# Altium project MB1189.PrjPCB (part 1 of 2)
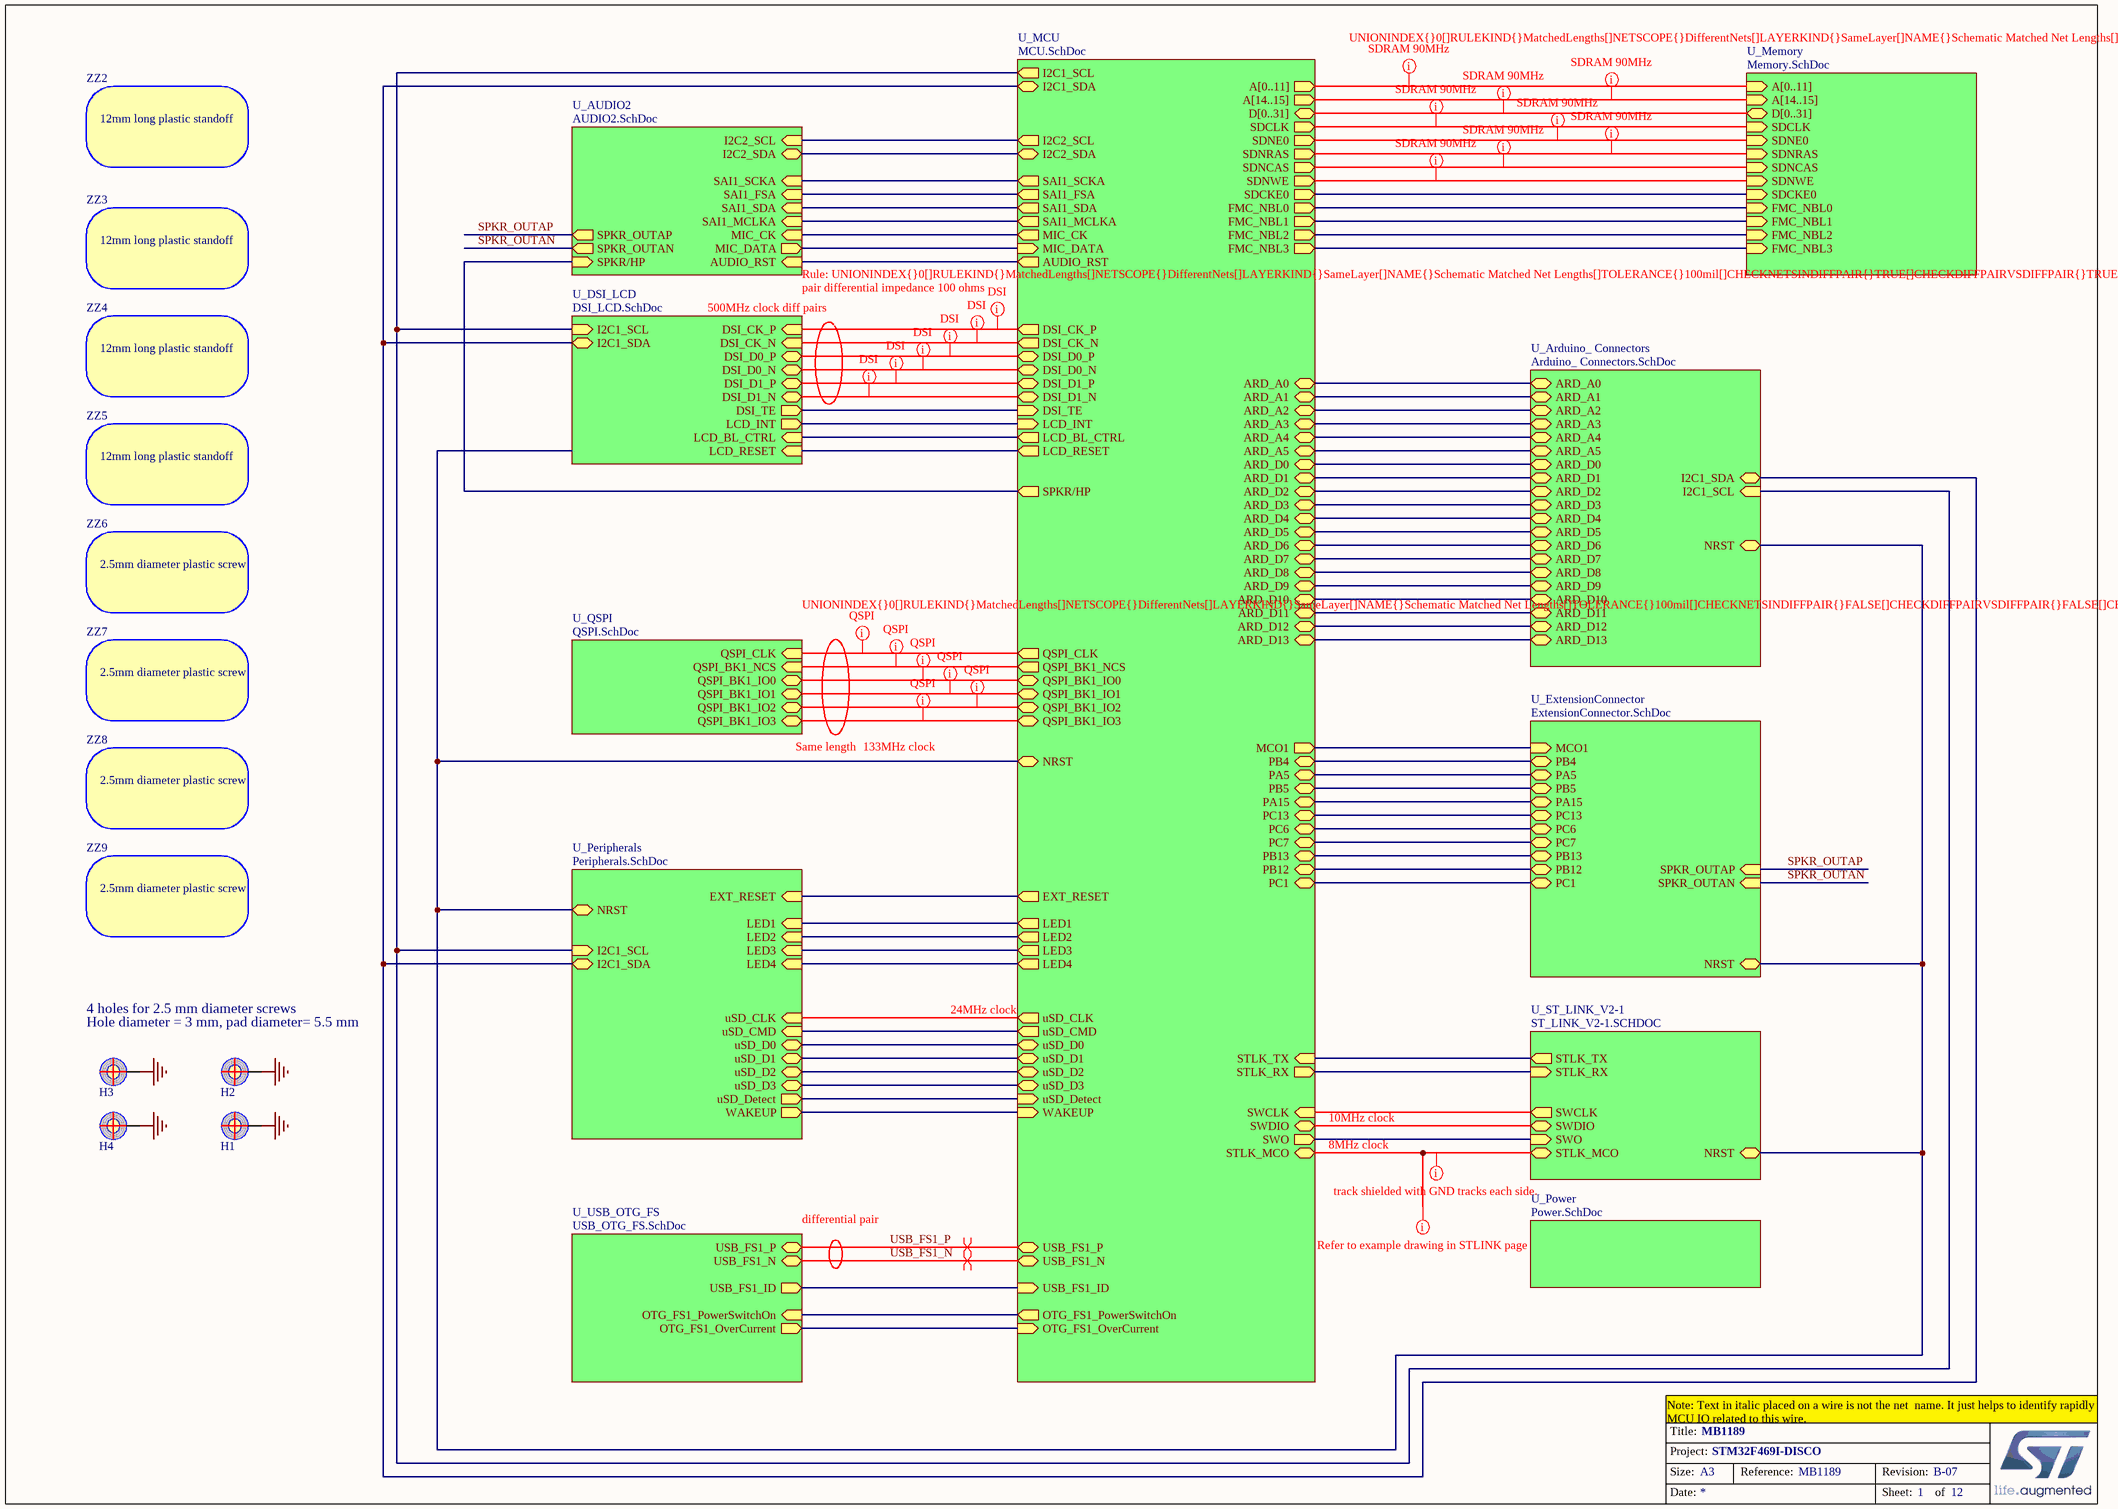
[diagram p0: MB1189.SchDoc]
12 sheets, 280 parts. Net scope: hierarchical (ports join the sheet entries above them; power ports are global).
Sheets:
  MB1189.SchDoc
    U_Memory = Memory.SchDoc
    U_Peripherals = Peripherals.SchDoc
    U_Power = Power.SchDoc
    U_ST_LINK_V2-1 = ST_LINK_V2-1.SCHDOC
    U_MCU = MCU.SchDoc
    U_Arduino_ Connectors = Arduino_ Connectors.SchDoc
    U_DSI_LCD = DSI_LCD.SchDoc
    U_QSPI = QSPI.SchDoc
    U_AUDIO2 = AUDIO2.SchDoc
    U_USB_OTG_FS = USB_OTG_FS.SchDoc
    U_ExtensionConnector = ExtensionConnector.SchDoc

## Sheet MB1189.SchDoc: MB1189
size A3; Date: 9/24/2014; Author: P.A.; CompanyName: STMicroelectronics; Organization: Microcontrollers Division; Address1: 12, Rue Jules HOROWITZ; Address2: 38019 Grenoble; Address3: FRANCE; DocumentNumber: MB1189; Revision: B-07; SheetNumber: 1; SheetTotal: 12; Project: STM32F469I-DISCO

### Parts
H1  POSITION HOLE  [HOLE_C5R5D3]  (value not drawn)
H2  POSITION HOLE  [HOLE_C5R5D3]  (value not drawn)
H3  POSITION HOLE  [HOLE_C5R5D3]  (value not drawn)
H4  POSITION HOLE  [HOLE_C5R5D3]  (value not drawn)
ZZ2  12mm long plastic standoff
ZZ3  12mm long plastic standoff
ZZ4  12mm long plastic standoff
ZZ5  12mm long plastic standoff
ZZ6  2.5mm diameter plastic screw
ZZ7  2.5mm diameter plastic screw
ZZ8  2.5mm diameter plastic screw
ZZ9  2.5mm diameter plastic screw

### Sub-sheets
U_Arduino_ Connectors = Arduino_ Connectors.SchDoc: I2C1_SDA (bidir), ARD_A0 (bidir), ARD_A1 (bidir), ARD_A2 (bidir), ARD_A3 (bidir), ARD_A4 (bidir), ARD_A5 (bidir), ARD_D5 (bidir), ARD_D4 (bidir), ARD_D3 (bidir), ARD_D2 (bidir), ARD_D1 (bidir), ARD_D0 (bidir), ARD_D13 (bidir), ARD_D12 (bidir), ARD_D11 (bidir), ARD_D10 (bidir), ARD_D9 (bidir), ARD_D8 (bidir), ARD_D6 (bidir), ARD_D7 (bidir), I2C1_SCL (in), NRST (bidir)
U_AUDIO2 = AUDIO2.SchDoc: SAI1_SCKA (in), SAI1_FSA (in), SAI1_SDA (in), AUDIO_RST (in), SAI1_MCLKA (in), I2C2_SCL (in), I2C2_SDA (bidir), MIC_CK (in), MIC_DATA (out), SPKR_OUTAP (out), SPKR_OUTAN (out), SPKR/HP (in)
U_DSI_LCD = DSI_LCD.SchDoc: DSI_CK_P (in), DSI_CK_N (in), DSI_D0_P (bidir), DSI_D0_N (bidir), DSI_D1_P (bidir), DSI_D1_N (bidir), DSI_TE (out), I2C1_SDA (bidir), I2C1_SCL (in), LCD_BL_CTRL (in), LCD_INT (out), LCD_RESET (in)
U_ExtensionConnector = ExtensionConnector.SchDoc: SPKR_OUTAP (in), SPKR_OUTAN (in), NRST (bidir), MCO1 (in), PB4 (bidir), PA5 (bidir), PB5 (bidir), PA15 (bidir), PC13 (bidir), PC7 (bidir), PC6 (bidir), PB13 (bidir), PB12 (bidir), PC1 (bidir)
U_MCU = MCU.SchDoc: LCD_BL_CTRL (out), MIC_CK (out), I2C1_SCL (out), I2C1_SDA (bidir), uSD_D0 (bidir), uSD_D1 (bidir), uSD_D2 (bidir), EXT_RESET (out), uSD_D3 (bidir), uSD_CLK (out), uSD_CMD (out), FMC_NBL3 (out), FMC_NBL2 (out), FMC_NBL0 (out), FMC_NBL1 (out), SAI1_SDA (out), SAI1_SCKA (out), SAI1_FSA (out), SAI1_MCLKA (out), SDNRAS (out), SDCLK (out), SDNCAS (out), SDCKE0 (out), SDNE0 (out), SDNWE (out), D[0..31] (bidir), QSPI_CLK (out), QSPI_BK1_NCS (out), QSPI_BK1_IO3 (bidir), QSPI_BK1_IO2 (bidir), QSPI_BK1_IO1 (bidir), QSPI_BK1_IO0 (bidir), WAKEUP (in), DSI_TE (in), DSI_CK_P (out), DSI_CK_N (out), DSI_D0_P (bidir), DSI_D0_N (bidir), DSI_D1_P (bidir), DSI_D1_N (bidir), NRST (bidir), LCD_INT (in), LED1 (out), LED2 (out), LED3 (out), LED4 (out), uSD_Detect (in), STLK_TX (in), STLK_RX (out), ARD_D5 (bidir), ARD_D4 (bidir), ARD_D3 (bidir), ARD_D2 (bidir), ARD_D1 (bidir), ARD_D0 (bidir), ARD_D13 (bidir), ARD_D12 (bidir), ARD_D11 (bidir), ARD_D10 (bidir), ARD_D9 (bidir), ARD_D8 (bidir), ARD_D6 (bidir), ARD_D7 (bidir), ARD_A0 (bidir), ARD_A1 (bidir), ARD_A2 (bidir), ARD_A3 (bidir), ARD_A4 (bidir), ARD_A5 (bidir), SWCLK (in), SWO (out), AUDIO_RST (out), USB_FS1_ID (in), OTG_FS1_PowerSwitchOn (out), OTG_FS1_OverCurrent (in), I2C2_SCL (out), I2C2_SDA (bidir), MIC_DATA (in), MCO1 (out), USB_FS1_N (bidir), USB_FS1_P (bidir), SWDIO, SPKR/HP (out), A[0..11] (out), A[14..15] (out), PB4 (bidir), PB5 (bidir), PA5 (bidir), PA15 (bidir), PC7 (bidir), PC6 (bidir), PC13 (bidir), PB12 (bidir), PB13 (bidir), PC1 (bidir), LCD_RESET (out), STLK_MCO
U_Memory = Memory.SchDoc: FMC_NBL0 (in), FMC_NBL1 (in), D[0..31] (bidir), SDNCAS (in), SDNWE (in), SDNRAS (in), SDNE0 (in), SDCKE0 (in), SDCLK (in), FMC_NBL3 (in), FMC_NBL2 (in), A[0..11] (in), A[14..15] (in)
U_Peripherals = Peripherals.SchDoc: uSD_CLK (in), uSD_CMD (in), uSD_D0 (bidir), uSD_D1 (bidir), uSD_D2 (bidir), uSD_D3 (bidir), WAKEUP (out), EXT_RESET (in), LED1 (in), LED2 (in), LED3 (in), LED4 (in), NRST (bidir), uSD_Detect (out), I2C1_SDA (bidir), I2C1_SCL (in)
U_Power = Power.SchDoc: no entries
U_QSPI = QSPI.SchDoc: QSPI_BK1_IO0 (bidir), QSPI_BK1_IO2 (bidir), QSPI_BK1_IO1 (bidir), QSPI_CLK (in), QSPI_BK1_NCS (in), QSPI_BK1_IO3 (bidir)
U_ST_LINK_V2-1 = ST_LINK_V2-1.SCHDOC: STLK_RX (in), STLK_TX (out), SWDIO, SWO (in), SWCLK (out), NRST (bidir), STLK_MCO
U_USB_OTG_FS = USB_OTG_FS.SchDoc: OTG_FS1_PowerSwitchOn (in), OTG_FS1_OverCurrent (out), USB_FS1_ID (out), USB_FS1_N (bidir), USB_FS1_P (bidir)

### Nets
GND: H1.1 H2.1 H3.1 H4.1
AUDIO_RST: sheet U_MCU/AUDIO_RST, sheet U_AUDIO2/AUDIO_RST
HSSI_CLK_N: sheet U_MCU/DSI_CK_N, sheet U_DSI_LCD/DSI_CK_N
HSSI_CLK_P: sheet U_MCU/DSI_CK_P, sheet U_DSI_LCD/DSI_CK_P
HSSI_D0_N: sheet U_MCU/DSI_D0_N, sheet U_DSI_LCD/DSI_D0_N
HSSI_D0_P: sheet U_MCU/DSI_D0_P, sheet U_DSI_LCD/DSI_D0_P
HSSI_D1_N: sheet U_MCU/DSI_D1_N, sheet U_DSI_LCD/DSI_D1_N
HSSI_D1_P: sheet U_MCU/DSI_D1_P, sheet U_DSI_LCD/DSI_D1_P
I2C1_SCL: sheet U_Peripherals/I2C1_SCL, sheet U_MCU/I2C1_SCL, sheet U_Arduino_ Connectors/I2C1_SCL, sheet U_DSI_LCD/I2C1_SCL
I2C1_SDA: sheet U_Peripherals/I2C1_SDA, sheet U_MCU/I2C1_SDA, sheet U_Arduino_ Connectors/I2C1_SDA, sheet U_DSI_LCD/I2C1_SDA
I2C2_SCL: sheet U_MCU/I2C2_SCL, sheet U_AUDIO2/I2C2_SCL
I2C2_SDA: sheet U_MCU/I2C2_SDA, sheet U_AUDIO2/I2C2_SDA
LCD_BL_CTRL: sheet U_MCU/LCD_BL_CTRL, sheet U_DSI_LCD/LCD_BL_CTRL
LCD_INT: sheet U_MCU/LCD_INT, sheet U_DSI_LCD/LCD_INT
LCD_RST: sheet U_MCU/LCD_RESET, sheet U_DSI_LCD/LCD_RESET
NRST: sheet U_Peripherals/NRST, sheet U_ST_LINK_V2-1/NRST, sheet U_MCU/NRST, sheet U_Arduino_ Connectors/NRST, sheet U_ExtensionConnector/NRST
PA0: sheet U_Peripherals/WAKEUP, sheet U_MCU/WAKEUP
PA1: sheet U_MCU/ARD_D3, sheet U_Arduino_ Connectors/ARD_D3
PA2: sheet U_MCU/ARD_D5, sheet U_Arduino_ Connectors/ARD_D5
PA4: sheet U_MCU/ARD_A5, sheet U_Arduino_ Connectors/ARD_A5
PA5: sheet U_MCU/PA5, sheet U_ExtensionConnector/PA5
PA6: sheet U_MCU/ARD_D6, sheet U_Arduino_ Connectors/ARD_D6
PA7: sheet U_MCU/ARD_D9, sheet U_Arduino_ Connectors/ARD_D9
PA8: sheet U_MCU/MCO1, sheet U_ExtensionConnector/MCO1
PA10: sheet U_MCU/USB_FS1_ID, sheet U_USB_OTG_FS/USB_FS1_ID
PA13: sheet U_ST_LINK_V2-1/SWDIO, sheet U_MCU/SWDIO
PA14: sheet U_ST_LINK_V2-1/SWCLK, sheet U_MCU/SWCLK
PA15: sheet U_MCU/PA15, sheet U_ExtensionConnector/PA15
PB0: sheet U_Peripherals/EXT_RESET, sheet U_MCU/EXT_RESET
PB1: sheet U_MCU/ARD_A0, sheet U_Arduino_ Connectors/ARD_A0
PB2: sheet U_MCU/OTG_FS1_PowerSwitchOn, sheet U_USB_OTG_FS/OTG_FS1_PowerSwitchOn
PB4: sheet U_MCU/PB4, sheet U_ExtensionConnector/PB4
PB5: sheet U_MCU/PB5, sheet U_ExtensionConnector/PB5
PB6: sheet U_MCU/QSPI_BK1_NCS, sheet U_QSPI/QSPI_BK1_NCS
PB7: sheet U_MCU/OTG_FS1_OverCurrent, sheet U_USB_OTG_FS/OTG_FS1_OverCurrent
PB10: sheet U_ST_LINK_V2-1/STLK_RX, sheet U_MCU/STLK_RX
PB11: sheet U_ST_LINK_V2-1/STLK_TX, sheet U_MCU/STLK_TX
PB12: sheet U_MCU/PB12, sheet U_ExtensionConnector/PB12
PB13: sheet U_MCU/PB13, sheet U_ExtensionConnector/PB13
PB14: sheet U_MCU/ARD_D12, sheet U_Arduino_ Connectors/ARD_D12
PB15: sheet U_MCU/ARD_D11, sheet U_Arduino_ Connectors/ARD_D11
PC0: sheet U_Memory/SDNWE, sheet U_MCU/SDNWE
PC1: sheet U_MCU/PC1, sheet U_ExtensionConnector/PC1
PC2: sheet U_MCU/ARD_A1, sheet U_Arduino_ Connectors/ARD_A1
PC3: sheet U_MCU/ARD_A2, sheet U_Arduino_ Connectors/ARD_A2
PC4: sheet U_MCU/ARD_A3, sheet U_Arduino_ Connectors/ARD_A3
PC5: sheet U_MCU/ARD_A4, sheet U_Arduino_ Connectors/ARD_A4
PC6: sheet U_MCU/PC6, sheet U_ExtensionConnector/PC6
PC7: sheet U_MCU/PC7, sheet U_ExtensionConnector/PC7
PC8: sheet U_Peripherals/uSD_D0, sheet U_MCU/uSD_D0
PC10: sheet U_Peripherals/uSD_D2, sheet U_MCU/uSD_D2
PC11: sheet U_Peripherals/uSD_D3, sheet U_MCU/uSD_D3
PC12: sheet U_Peripherals/uSD_CLK, sheet U_MCU/uSD_CLK
PC13: sheet U_MCU/PC13, sheet U_ExtensionConnector/PC13
PD2: sheet U_Peripherals/uSD_CMD, sheet U_MCU/uSD_CMD
PD3: sheet U_MCU/ARD_D13, sheet U_Arduino_ Connectors/ARD_D13
PD4: sheet U_Peripherals/LED2, sheet U_MCU/LED2
PD5: sheet U_Peripherals/LED3, sheet U_MCU/LED3
PD6: sheet U_MCU/MIC_DATA, sheet U_AUDIO2/MIC_DATA
PE0: sheet U_Memory/FMC_NBL0, sheet U_MCU/FMC_NBL0
PE1: sheet U_Memory/FMC_NBL1, sheet U_MCU/FMC_NBL1
PE3: sheet U_MCU/SPKR/HP, sheet U_AUDIO2/SPKR/HP
PE4: sheet U_MCU/SAI1_FSA, sheet U_AUDIO2/SAI1_FSA
PE5: sheet U_MCU/SAI1_SCKA, sheet U_AUDIO2/SAI1_SCKA
PE6: sheet U_MCU/SAI1_SDA, sheet U_AUDIO2/SAI1_SDA
PF6: sheet U_MCU/QSPI_BK1_IO3, sheet U_QSPI/QSPI_BK1_IO3
PF7: sheet U_MCU/QSPI_BK1_IO2, sheet U_QSPI/QSPI_BK1_IO2
PF8: sheet U_MCU/QSPI_BK1_IO0, sheet U_QSPI/QSPI_BK1_IO0
PF9: sheet U_MCU/QSPI_BK1_IO1, sheet U_QSPI/QSPI_BK1_IO1
PF10: sheet U_MCU/QSPI_CLK, sheet U_QSPI/QSPI_CLK
PF11: sheet U_Memory/SDNRAS, sheet U_MCU/SDNRAS
PG2: sheet U_Peripherals/uSD_Detect, sheet U_MCU/uSD_Detect
PG6: sheet U_Peripherals/LED1, sheet U_MCU/LED1
PG7: sheet U_MCU/SAI1_MCLKA, sheet U_AUDIO2/SAI1_MCLKA
PG8: sheet U_Memory/SDCLK, sheet U_MCU/SDCLK
PG9: sheet U_MCU/ARD_D0, sheet U_Arduino_ Connectors/ARD_D0
PG10: sheet U_MCU/ARD_D8, sheet U_Arduino_ Connectors/ARD_D8
PG11: sheet U_MCU/ARD_D7, sheet U_Arduino_ Connectors/ARD_D7
PG12: sheet U_MCU/ARD_D4, sheet U_Arduino_ Connectors/ARD_D4
PG13: sheet U_MCU/ARD_D2, sheet U_Arduino_ Connectors/ARD_D2
PG14: sheet U_MCU/ARD_D1, sheet U_Arduino_ Connectors/ARD_D1
PG15: sheet U_Memory/SDNCAS, sheet U_MCU/SDNCAS
PH2: sheet U_Memory/SDCKE0, sheet U_MCU/SDCKE0
PH3: sheet U_Memory/SDNE0, sheet U_MCU/SDNE0
PH6: sheet U_MCU/ARD_D10, sheet U_Arduino_ Connectors/ARD_D10
PI4: sheet U_Memory/FMC_NBL2, sheet U_MCU/FMC_NBL2
PI5: sheet U_Memory/FMC_NBL3, sheet U_MCU/FMC_NBL3
PJ2: sheet U_MCU/DSI_TE, sheet U_DSI_LCD/DSI_TE
PK3: sheet U_Peripherals/LED4, sheet U_MCU/LED4
SPKR_OUTAN: sheet U_AUDIO2/SPKR_OUTAN, sheet U_ExtensionConnector/SPKR_OUTAN
SPKR_OUTAP: sheet U_AUDIO2/SPKR_OUTAP, sheet U_ExtensionConnector/SPKR_OUTAP
USB_FS1_N: sheet U_MCU/USB_FS1_N, sheet U_USB_OTG_FS/USB_FS1_N
USB_FS1_P: sheet U_MCU/USB_FS1_P, sheet U_USB_OTG_FS/USB_FS1_P
NetC26_1: sheet U_ST_LINK_V2-1/STLK_MCO, sheet U_MCU/STLK_MCO
NetCN9_8: sheet U_Peripherals/uSD_D1, sheet U_MCU/uSD_D1
NetR87_1: sheet U_MCU/MIC_CK, sheet U_AUDIO2/MIC_CK
NetSB3_2: sheet U_ST_LINK_V2-1/SWO, sheet U_MCU/SWO

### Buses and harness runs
bus sheet U_MCU/A[0..11] = sheet U_Memory/A[0..11]
bus sheet U_MCU/A[14..15] = sheet U_Memory/A[14..15]
bus sheet U_MCU/D[0..31] = sheet U_Memory/D[0..31]

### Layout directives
rule Matched Net Lengths [Tolerance = 250mil]: (no net found under the mark), PC0, PF11, PG8, PG15, PH3
rule Matched Net Lengths [Tolerance = 100mil]; rule ? : HSSI_CLK_N, HSSI_CLK_P, HSSI_D0_N, HSSI_D0_P, HSSI_D1_N, HSSI_D1_P
rule Matched Net Lengths [Tolerance = 100mil]: PB6, PF6, PF7, PF8, PF9, PF10
differential pair: USB_FS1_N, USB_FS1_P
mark named track shielded with GND tracks each side.: NetC26_1
mark named Refer to example drawing in STLINK page: NetC26_1

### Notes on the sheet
- 500MHz clock diff pairs
- Same length
- 133MHz clock
- 4 holes for 2.5 mm diameter screws
- Hole diameter = 3 mm, pad diameter= 5.5 mm
- 24MHz clock
- 10MHz clock
- 8MHz clock
- differential pair
- Note: Text in italic placed on a wire is not the net  name. It just helps to identify rapidly MCU IO related to this wire.

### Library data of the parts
H1-H4 = POSITION HOLE: Ordered by: Subcon
ZZ2-ZZ9 = BoM_Item: Heigth Spacer; Ordered by: Subcon; Assembly: assembled at each corner

## Sheet Memory.SchDoc: SDRAM
size A4; Date: 9/24/2014; Author: P.A.; CompanyName: STMicroelectronics; Organization: Microcontrollers Division; Address1: 12, Rue Jules HOROWITZ; Address2: 38019 Grenoble; Address3: FRANCE; DocumentNumber: MB1189; Revision: B-07; SheetNumber: 8; SheetTotal: 12; Project: STM32F469I-DISCO
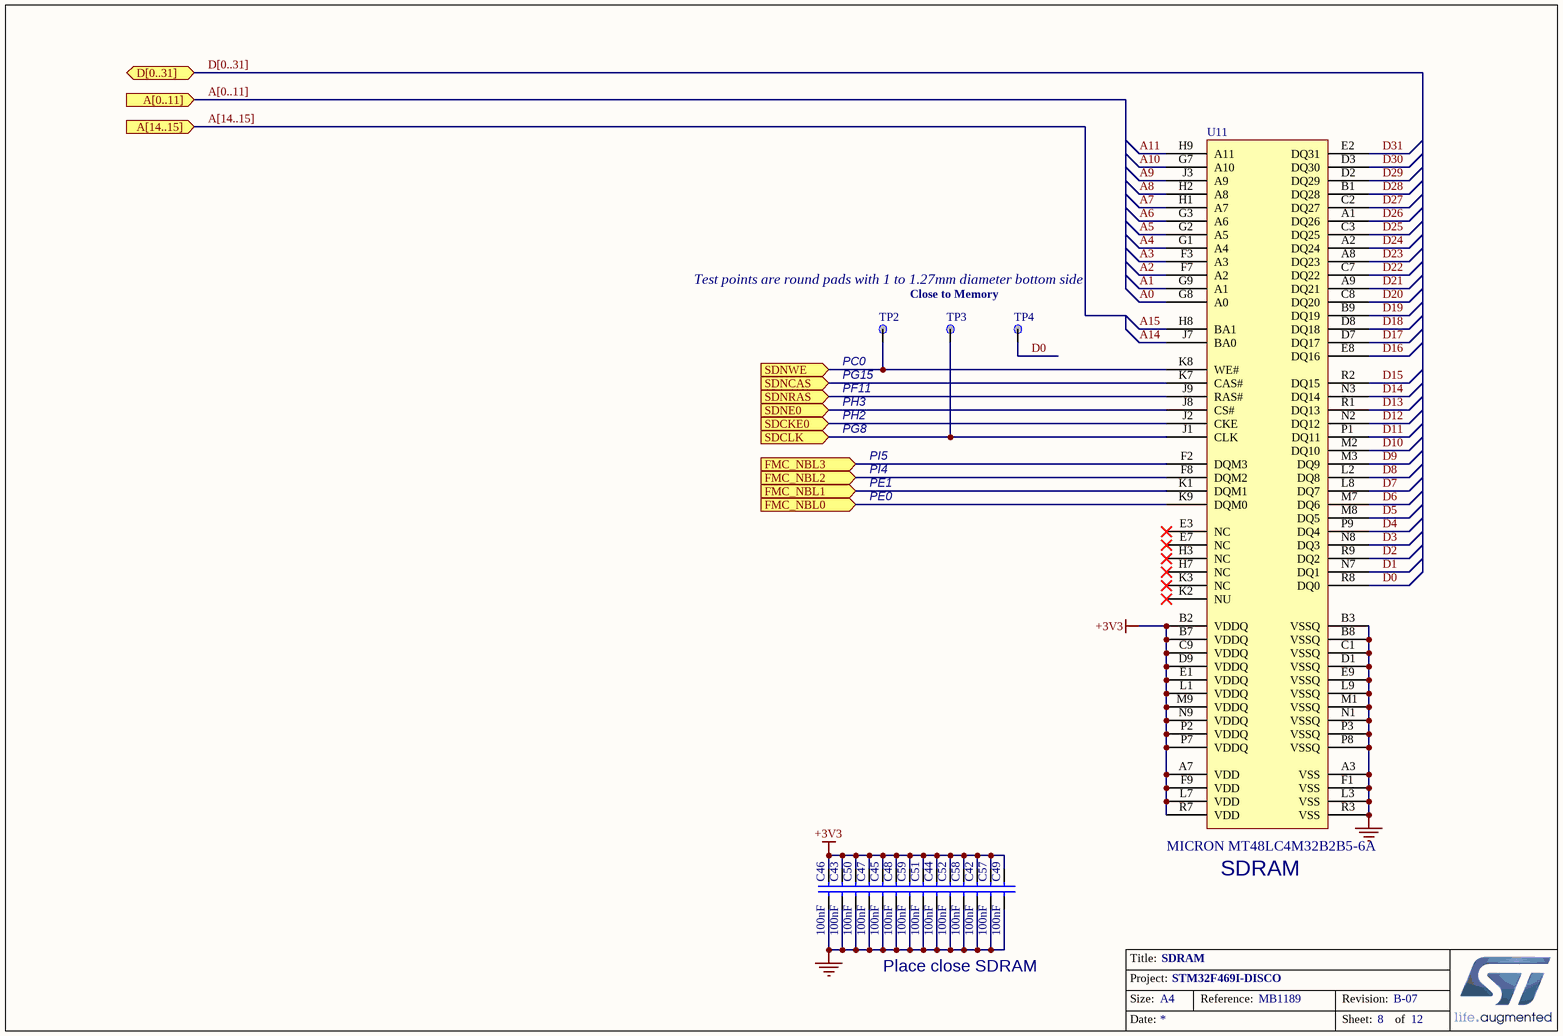
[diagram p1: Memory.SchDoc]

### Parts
C42  100nF  [0402C]
C43  100nF  [0402C]
C44  100nF  [0402C]
C45  100nF  [0402C]
C46  100nF  [0402C]
C47  100nF  [0402C]
C48  100nF  [0402C]
C49  100nF  [0402C]
C50  100nF  [0402C]
C51  100nF  [0402C]
C52  100nF  [0402C]
C57  100nF  [0402C]
C58  100nF  [0402C]
C59  100nF  [0402C]
TP2  TP  [TP_C40]  (value not drawn)
TP3  TP  [TP_C40]  (value not drawn)
TP4  TP  [TP_C40]  (value not drawn)
U11  MICRON MT48LC4M32B2B5-6A  [FBGA90_0R8_8X13]

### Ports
A[0..11] (in), A[14..15] (in), D[0..31] (bidir), FMC_NBL0 (in), FMC_NBL1 (in), FMC_NBL2 (in), FMC_NBL3 (in), SDCKE0 (in), SDCLK (in), SDNCAS (in), SDNE0 (in), SDNRAS (in), SDNWE (in)

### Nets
+3V3: C42.1 C43.1 C44.1 C45.1 C46.1 C47.1 C48.1 C49.1 C50.1 C51.1 C52.1 C57.1 C58.1 C59.1 U11.A7(VDD) U11.B2(VDDQ) U11.B7(VDDQ) U11.C9(VDDQ) U11.D9(VDDQ) U11.E1(VDDQ) U11.F9(VDD) U11.L1(VDDQ) U11.L7(VDD) U11.M9(VDDQ) U11.N9(VDDQ) U11.P2(VDDQ) U11.P7(VDDQ) U11.R7(VDD)
GND: C42.2 C43.2 C44.2 C45.2 C46.2 C47.2 C48.2 C49.2 C50.2 C51.2 C52.2 C57.2 C58.2 C59.2 U11.A3(VSS) U11.B3(VSSQ) U11.B8(VSSQ) U11.C1(VSSQ) U11.D1(VSSQ) U11.E9(VSSQ) U11.F1(VSS) U11.L3(VSS) U11.L9(VSSQ) U11.M1(VSSQ) U11.N1(VSSQ) U11.P3(VSSQ) U11.P8(VSSQ) U11.R3(VSS)
A0: U11.G8(A0)
A1: U11.G9(A1)
A2: U11.F7(A2)
A3: U11.F3(A3)
A4: U11.G1(A4)
A5: U11.G2(A5)
A6: U11.G3(A6)
A7: U11.H1(A7)
A8: U11.H2(A8)
A9: U11.J3(A9)
A10: U11.G7(A10)
A11: U11.H9(A11)
A14: U11.J7(BA0)
A15: U11.H8(BA1)
D0: TP4.1 U11.R8(DQ0)
D1: U11.N7(DQ1)
D2: U11.R9(DQ2)
D3: U11.N8(DQ3)
D4: U11.P9(DQ4)
D5: U11.M8(DQ5)
D6: U11.M7(DQ6)
D7: U11.L8(DQ7)
D8: U11.L2(DQ8)
D9: U11.M3(DQ9)
D10: U11.M2(DQ10)
D11: U11.P1(DQ11)
D12: U11.N2(DQ12)
D13: U11.R1(DQ13)
D14: U11.N3(DQ14)
D15: U11.R2(DQ15)
D16: U11.E8(DQ16)
D17: U11.D7(DQ17)
D18: U11.D8(DQ18)
D19: U11.B9(DQ19)
D20: U11.C8(DQ20)
D21: U11.A9(DQ21)
D22: U11.C7(DQ22)
D23: U11.A8(DQ23)
D24: U11.A2(DQ24)
D25: U11.C3(DQ25)
D26: U11.A1(DQ26)
D27: U11.C2(DQ27)
D28: U11.B1(DQ28)
D29: U11.D2(DQ29)
D30: U11.D3(DQ30)
D31: U11.E2(DQ31)
PC0: TP2.1 U11.K8(WE#) ; port SDNWE
PE0: U11.K9(DQM0) ; port FMC_NBL0
PE1: U11.K1(DQM1) ; port FMC_NBL1
PF11: U11.J9(RAS#) ; port SDNRAS
PG8: TP3.1 U11.J1(CLK) ; port SDCLK
PG15: U11.K7(CAS#) ; port SDNCAS
PH2: U11.J2(CKE) ; port SDCKE0
PH3: U11.J8(CS#) ; port SDNE0
PI4: U11.F8(DQM2) ; port FMC_NBL2
PI5: U11.F2(DQM3) ; port FMC_NBL3

Not connected (* = marked no-connect by the designer): U11 E3(NC)* E7(NC)* H3(NC)* H7(NC)* K2(NU)* K3(NC)*

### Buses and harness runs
bus A[0..11] = port A[0..11]
bus A[14..15] = port A[14..15]
bus D[0..31] = port D[0..31]

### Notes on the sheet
- Test points are round pads with 1 to 1.27mm diameter bottom side
- Close to Memory
- (near TP2) PC0
- (near TP2) PG15
- PF11
- PH3
- PH2
- PG8
- PE1
- PE0
- PI5
- PI4
- (near U11) SDRAM
- Place close SDRAM

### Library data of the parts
C42-C52 C57-C59 = Cap: Capacitor; Value: 10nF; Ordered by: Subcon
TP2-TP4 = TP: Ordered by: Subcon
U11 = MT48LC4M32B2B5: Ordered by: Subcon; ECCN_US/EU: EAR99/NEC

## Sheet Peripherals.SchDoc: Peripherals
size A4; Date: 9/24/2014; Author: P.A.; CompanyName: STMicroelectronics; Organization: Microcontrollers Division; Address1: 12, Rue Jules HOROWITZ; Address2: 38019 Grenoble; Address3: FRANCE; DocumentNumber: MB1189; Revision: B-07; SheetNumber: 5; SheetTotal: 12; Project: STM32F469I-DISCO
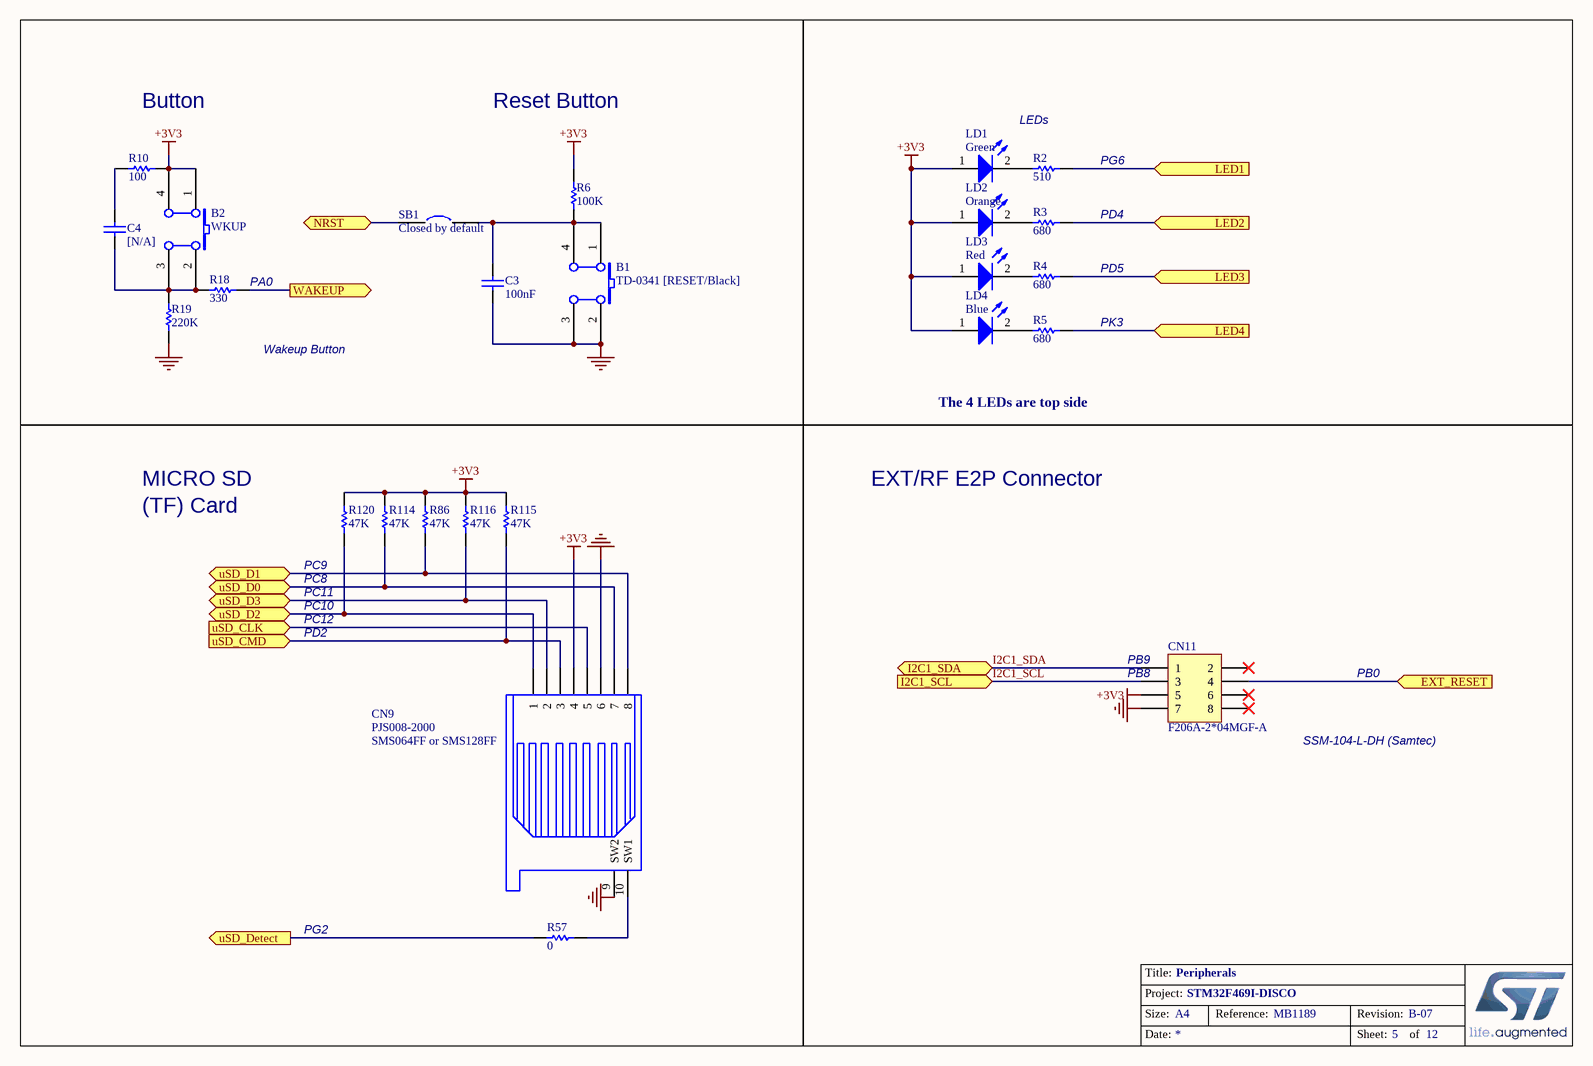
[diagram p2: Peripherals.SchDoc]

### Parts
B1  TD-0341 [RESET/Black]  [PB10]
B2  WKUP  [PB10]
C3  100nF  [0402C]
C4  [N/A]  [0603C]
CN9  PJS008-2000  [MSD_PJS008_]
CN11  F206A-2*04MGF-A  [SSM-104-L-DH]
LD1  Green  [0603D]
LD2  Orange  [0603D]
LD3  Red  [0603D]
LD4  Blue  [0603D]
R2  510  [0603R]
R3  680  [0603R]
R4  680  [0603R]
R5  680  [0603R]
R6  100K  [0603R]
R10  100  [0603R]
R18  330  [0603R]
R19  220K  [0603R]
R57  0  [0603R]
R86  47K  [0603R]
R114  47K  [0603R]
R115  47K  [0603R]
R116  47K  [0603R]
R120  47K  [0603R]
SB1  Closed by default  [SB_0603]

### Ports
EXT_RESET (in), I2C1_SCL (in), I2C1_SDA (bidir), LED1 (in), LED2 (in), LED3 (in), LED4 (in), NRST (bidir), uSD_CLK (in), uSD_CMD (in), uSD_D0 (bidir), uSD_D1 (bidir), uSD_D2 (bidir), uSD_D3 (bidir), uSD_Detect (out), WAKEUP (out)

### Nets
+3V3: B2.1(A0) B2.4(A1) CN9.4 CN11.5 LD1.1(A) LD2.1(A) LD3.1(A) LD4.1(A) R6.1 R10.1 R86.1 R114.1 R115.1 R116.1 R120.1
GND: B1.2(B0) B1.3(B1) C3.1 CN9.6 CN9.9(SW2) CN11.7 R19.2
I2C1_SCL: CN11.3 ; port I2C1_SCL
I2C1_SDA: CN11.1 ; port I2C1_SDA
NRST: SB1.1 ; port NRST
PA0: R18.2 ; port WAKEUP
PB0: CN11.4 ; port EXT_RESET
PC8: CN9.7 R114.2 ; port uSD_D0
PC10: CN9.1 R120.2 ; port uSD_D2
PC11: CN9.2 R116.2 ; port uSD_D3
PC12: CN9.5 ; port uSD_CLK
PD2: CN9.3 R115.2 ; port uSD_CMD
PD4: R3.1 ; port LED2
PD5: R4.1 ; port LED3
PG2: R57.1 ; port uSD_Detect
PG6: R2.1 ; port LED1
PK3: R5.1 ; port LED4
NetB1_1: B1.1(A0) B1.4(A1) C3.2 R6.2 SB1.2
NetB2_2: B2.2(B0) B2.3(B1) C4.2 R18.1 R19.1
NetC4_1: C4.1 R10.2
NetCN9_8: CN9.8 R86.2 ; port uSD_D1
NetCN9_10: CN9.10(SW1) R57.2
NetLD1_2: LD1.2(K) R2.2
NetLD2_2: LD2.2(K) R3.2
NetLD3_2: LD3.2(K) R4.2
NetLD4_2: LD4.2(K) R5.2

Not connected (* = marked no-connect by the designer): CN11 2* 6* 8*

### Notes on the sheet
- Button
- Reset Button
- LEDs
- (near R2) PG6
- PD4
- (near R18) PA0
- PD5
- PK3
- Wakeup Button
- The 4 LEDs are top side
- MICRO SD
- (TF) Card
- EXT/RF E2P Connector
- (near R120) PC8
- (near R120) PC9
- PC11
- PC10
- PC12
- PD2
- (near CN11) PB9
- (near CN11) PB8
- PB0
- (near CN9) SMS064FF or SMS128FF
- (near CN11) SSM-104-L-DH (Samtec)
- PG2

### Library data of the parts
B1 = SW PUSHBUTTON: SE PUSHBUTTON; Ordered by: Subcon; Assembly: with Back cap; Silkscreen: RESET
B2 = SW PUSHBUTTON: SE PUSHBUTTON; Ordered by: Subcon; Assembly: with Blue cap; Silkscreen: USER
C3 = CAP: Capacitor; Value: 100pF; Ordered by: Subcon
C4 = CAP: Capacitor; Value: 100pF; Ordered by: Subcon; Fitted: NO
CN9 = SMS016AFA5E: Manuf_1: Yamaichi; Ordered by: Subcon; Silkscreen: uSD
CN11 = SSM-104-L-DH: Header, 5-Pin, Dual row; Manuf_1: SAMTEC; Ordered by: Subcon; Silkscreen: RFEEPROM
LD1-LD4 = LED2: Typical RED, GREEN, YELLOW, AMBER GaAs LED; Ordered by: Subcon; ECCN_US/EU: EAR99/NEC
R2-R5 R10 R18 R57 = Res1: Resistor; Value: 1K; Ordered by: Subcon
R6 R19 R86 R114-R116 R120 = res1: Resistor; Value: 1K; Ordered by: Subcon
SB1 = Circuit Breaker: Ordered by: Subcon; Comments: Solder bridge

## Sheet Power.SchDoc: Power
size A4; Date: 9/24/2014; Author: P.A.; CompanyName: STMicroelectronics; Organization: Microcontrollers Division; Address1: 12, Rue Jules HOROWITZ; Address2: 38019 Grenoble; Address3: FRANCE; DocumentNumber: MB1189; Revision: B-07; SheetNumber: 4; SheetTotal: 12; Project: STM32F469I-DISCO
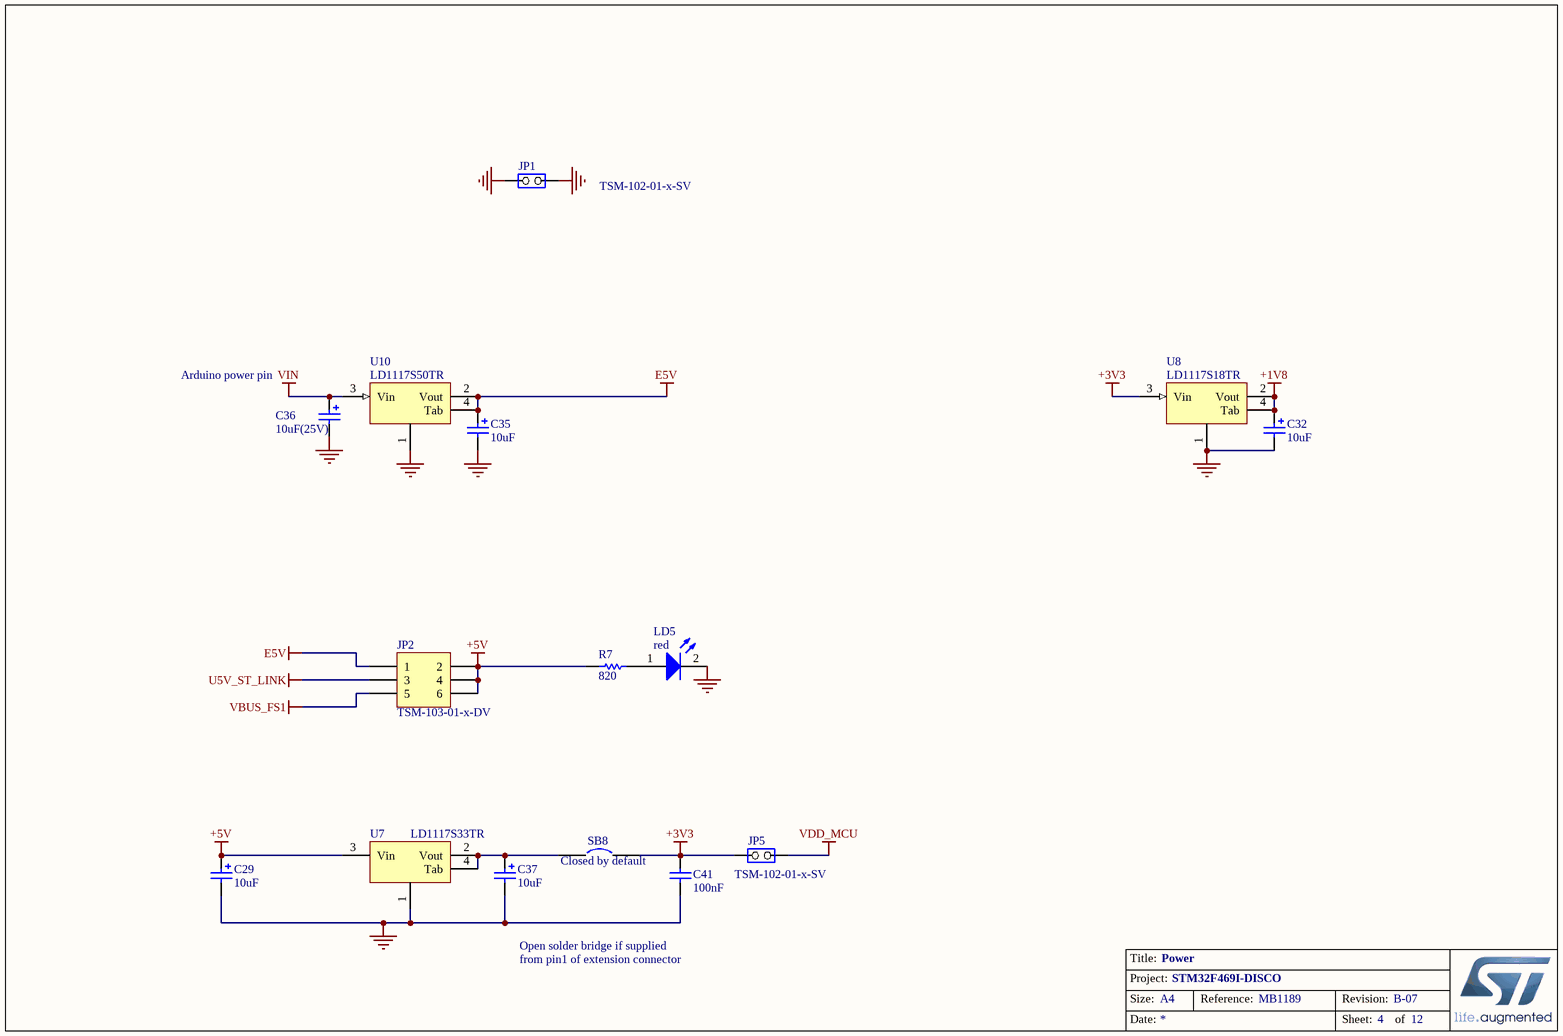
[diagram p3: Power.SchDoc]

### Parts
C29  10uF  [TAN-A]
C32  10uF  [TAN-A]
C35  10uF  [TAN-A]
C36  10uF(25V)  [TAN-B]
C37  10uF  [TAN-A]
C41  100nF  [0402C]
JP1  TSM-102-01-x-SV  [TSM-102-01-x-SV]
JP2  TSM-103-01-x-DV  [TSM-103-01-x-DV]
JP5  TSM-102-01-x-SV  [TSM-102-01-x-SV]
LD5  red  [0603D]
R7  820  [0603R]
SB8  Closed by default  [SB_0603]
U7  LD1117S33TR  [SOT-223]
U8  LD1117S18TR  [SOT-223]
U10  LD1117S50TR  [SOT-223]

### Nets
+1V8: C32.1 U8.2(Vout) U8.4(Tab)
+3V3: C41.1 JP5.1(COMMON) SB8.2 U8.3(Vin)
+5V: C29.1 JP2.2 JP2.4 JP2.6 R7.2 U7.3(Vin)
E5V: C35.1 JP2.1 U10.2(Vout) U10.4(Tab)
GND: C29.2 C32.2 C35.2 C36.2 C37.2 C41.2 JP1.1(COMMON) JP1.2(NO) LD5.2(K) U7.1 U8.1 U10.1
U5V_ST_LINK: JP2.3
VBUS_FS1: JP2.5
VDD_MCU: JP5.2(NO)
VIN: C36.1 U10.3(Vin)
NetC37_1: C37.1 SB8.1 U7.2(Vout) U7.4(Tab)
NetLD5_1: LD5.1(A) R7.1

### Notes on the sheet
- (near C36) Arduino power pin
- Open solder bridge if supplied
  from pin1 of extension connector

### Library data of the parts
C29 C32 C35-C37 = Cap Pol1: Polarized Capacitor (Radial); Ordered by: Subcon
C41 = Cap: as C42 on sheet Memory
JP1 = JP2: Manuf_1: SAMTEC; Ordered by: Subcon; Silkscreen: GND; Assembly: with jumper
JP2 = Header 3X2: Header, 3-Pin, Dual row; Manuf_1: SAMTEC; Ordered by: Subcon; Silkscreen: E5V:pins1,2 STLK: pins3,4 USB: pins 5,6; Assembly: 3,4 closed
JP5 = JP2: Manuf_1: SAMTEC; Ordered by: Subcon; Assembly: with jumper; Silkscreen: IDD
LD5 = LED2: Typical RED, GREEN, YELLOW, AMBER GaAs LED; Ordered by: Subcon; ECCN_US/EU: EAR99/NEC; Silkscreen: 5V
R7 = res1: Resistor; Value: 1K; Ordered by: Subcon
SB8 = Circuit Breaker: as SB1 on sheet Peripherals
U7 = LD1117S33TR: LOW DROP FIXED AND ADJUSTABLE POSITIVE VOLTAGE REGULATORS (3.3 Volts); Provided: ST; ECCN_US/EU: EAR99/NEC; Ref St: 9176186
U8 = LD1117: Ordered by: ST; ECCN_US/EU: EAR99/NEC; Ref St: 9176180
U10 = LD1117: Ordered by: ST; ECCN_US/EU: EAR99/NEC; Ref St: 9176133

## Sheet ST_LINK_V2-1.SCHDOC: ST-LINK/V2-1
size A4; Date: 9/24/2014; Author: P.A.; CompanyName: STMicroelectronics; Organization: Microcontrollers Division; Address1: 12, Rue Jules HOROWITZ; Address2: 38019 Grenoble; Address3: FRANCE; DocumentNumber: MB1189; Revision: B-07; SheetNumber: 12; SheetTotal: 12; Project: STM32F469I-DISCO
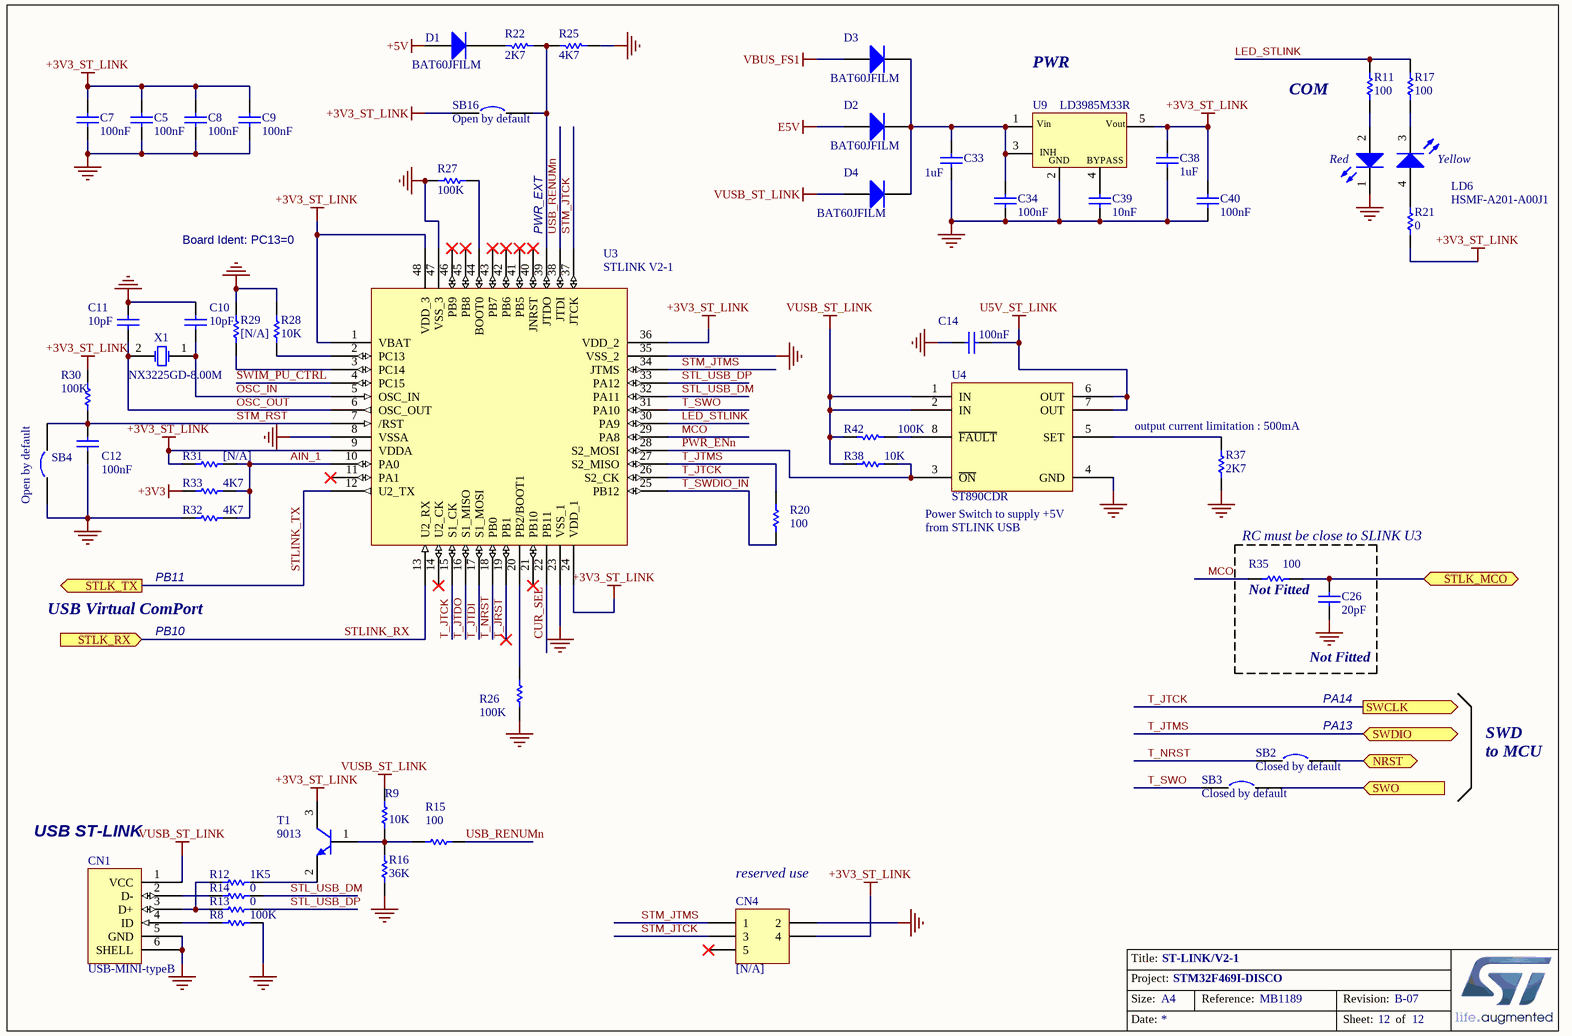
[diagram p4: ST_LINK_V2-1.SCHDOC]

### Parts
C5  100nF  [0402C]
C7  100nF  [0402C]
C8  100nF  [0402C]
C9  100nF  [0402C]
C10  10pF  [0603C]
C11  10pF  [0603C]
C12  100nF  [0402C]
C14  100nF  [0402C]
C26  20pF  [0603C]
C33  1uF  [0603C]
C34  100nF  [0402C]
C38  1uF  [0603C]
C39  10nF  [0603C]
C40  100nF  [0402C]
CN1  USB-MINI-typeB  [MINIUSB_AB_5SM_RA]
CN4  [N/A]  [HDR_2X3-1_2R54-6]
D1  BAT60JFILM  [SOD-323]
D2  BAT60JFILM  [SOD-323]
D3  BAT60JFILM  [SOD-323]
D4  BAT60JFILM  [SOD-323]
LD6  HSMF-A201-A00J1  [LED2_3528]
R8  100K  [0603R]
R9  10K  [0402R]
R11  100  [0603R]
R12  1K5  [0603R]
R13  0  [0603R]
R14  0  [0603R]
R15  100  [0603R]
R16  36K  [0603R]
R17  100  [0603R]
R20  100  [0603R]
R21  0  [0603R]
R22  2K7  [0603R]
R25  4K7  [0603R]
R26  100K  [0603R]
R27  100K  [0603R]
R28  10K  [0402R]
R29  [N/A]  [0603R]
R30  100K  [0603R]
R31  [N/A]  [0603R]
R32  4K7  [0603R]
R33  4K7  [0603R]
R35  100  [0603R]
R37  2K7  [0603R]
R38  10K  [0402R]
R42  100K  [0603R]
SB2  Closed by default  [SB_0603]
SB3  Closed by default  [SB_0603]
SB4  Open by default  [SB_0603]
SB16  Open by default  [SB_0603]
T1  9013  [SOT-23]
U3  STLINK V2-1  [LQFP48_0R5_9X9]
U4  ST890CDR  [SOIC8_1R27_4R9X6]
U9  LD3985M33R  [SOT23-5]
X1  NX3225GD-8.00M  [XTAL_2SM_3R2X2R5_H1]

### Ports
NRST (bidir), STLK_MCO, STLK_RX (in), STLK_TX (out), SWCLK (out), SWDIO, SWO (in)

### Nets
+3V3: R33.1
+3V3_ST_LINK: C5.2 C7.2 C8.2 C9.2 C38.1 C40.2 CN4.4 R21.2 R30.2 R31.1 SB16.1 T1.3(C) U3.1(VBAT) U3.9(VDDA) U3.24(VDD_1) U3.36(VDD_2) U3.48(VDD_3) U9.5(Vout)
+5V: D1.1(A)
E5V: D2.1(A)
GND: C5.1 C7.1 C8.1 C9.1 C10.2 C11.2 C12.1 C14.1 C26.2 C33.1 C34.1 C38.2 C39.1 C40.1 CN1.5(GND) CN1.6(SHELL) CN4.2 LD6.1(RED_cathode) R8.2 R16.1 R25.2 R26.1 R27.1 R28.1 R29.1 R32.1 R37.2 SB4.1 U3.8(VSSA) U3.23(VSS_1) U3.35(VSS_2) U3.47(VSS_3) U4.4(GND) U9.2(GND)
U5V_ST_LINK: C14.2 U4.6(OUT) U4.7(OUT)
VBUS_FS1: D3.1(A)
VUSB_ST_LINK: CN1.1(VCC) D4.1(A) R9.2 R38.1 R42.1 U4.1(IN) U4.2(IN)
AIN_1: R31.2 R32.2 R33.2 U3.10(PA0)
CUR_SEL: U3.22(PB11)
LED_STLINK: R11.1 R17.1 U3.30(PA9)
MCO: R35.1 U3.29(PA8)
NRST: SB2.2 ; port NRST
OSC_IN: C10.1 U3.5(OSC_IN) X1.1(OSC1)
OSC_OUT: C11.1 U3.6(OSC_OUT) X1.2(OSC2)
PWR_ENn: R38.2 U3.28(S2_MOSI) U4.3(~{ON})
STL_USB_DM: R14.2 U3.32(PA11)
STL_USB_DP: R13.2 U3.33(PA12)
STLINK_RX: U3.13(U2_RX) ; port STLK_RX  [project net PB10]
STLINK_TX: U3.12(U2_TX) ; port STLK_TX  [project net PB11]
STM_JTCK: CN4.3 U3.37(JTCK)
STM_JTMS: CN4.1 U3.34(JTMS)
STM_RST: C12.2 R30.1 SB4.2 U3.7(/RST)
SWIM_PU_CTRL: U3.4(PC15)
T_JRST: U3.19(PB1)
T_JTCK: U3.15(S1_CK) U3.26(S2_CK) ; port SWCLK  [project net PA14]
T_JTDI: U3.17(S1_MOSI)
T_JTDO: U3.16(S1_MISO)
T_JTMS: R20.2 U3.27(S2_MISO) ; port SWDIO  [project net PA13]
T_NRST: SB2.1 U3.18(PB0)
T_SWDIO_IN: R20.1 U3.25(PB12)
T_SWO: SB3.1 U3.31(PA10)
USB_RENUMn: R15.2 U3.38(JTDI)
NetC26_1: C26.1 R35.2 ; port STLK_MCO
NetC33_2: C33.2 C34.2 D2.2(K) D3.2(K) D4.2(K) U9.1(Vin) U9.3(CE)
NetC39_2: C39.2 U9.4(BYPASS)
NetCN1_2: CN1.2(D-) R14.1
NetCN1_3: CN1.3(D+) R12.1 R13.1
NetCN1_4: CN1.4(ID) R8.1
NetD1_2: D1.2(K) R22.1
NetLD6_2: LD6.2(Red_anode) R11.2
NetLD6_3: LD6.3(YellowGreen_cathode) R17.2
NetLD6_4: LD6.4(YellowGreen_anode) R21.1
NetR9_1: R9.1 R15.1 R16.2 T1.1(B)
NetR12_2: R12.2 T1.2(E)
NetR22_2: R22.2 R25.1 SB16.2 U3.39(JTDO)
NetR26_2: R26.2 U3.20(PB2/BOOT1)
NetR27_2: R27.2 U3.44(BOOT0)
NetR28_2: R28.2 U3.2(PC13)
NetR29_2: R29.2 U3.3(PC14)
NetR37_1: R37.1 U4.5(SET)
NetR42_2: R42.2 U4.8(~{FAULT})
NetSB3_2: SB3.2 ; port SWO

Not connected (* = marked no-connect by the designer): CN4 5*; U3 11(PA1)* 14(U2_CK)* 21(PB10)* 40(JNRST)* 41(PB5)* 42(PB6)* 43(PB7)* 45(PB8)* 46(PB9)*

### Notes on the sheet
- PWR
- COM
- Board Ident: PC13=0
- PWR_EXT
- (near R37) output current limitation : 500mA
- PB11
- (near U4) Power Switch to supply +5V from STLINK USB
- RC must be close to SLINK U3
- USB Virtual ComPort
- PB10
- Not Fitted
- (near C26) Not Fitted
- PA14
- (near SB2) PA13
- SWD
  to MCU
- (near CN1) USB ST-LINK
- (near CN4) reserved use

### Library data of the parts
C5 C7-C9 C12 C14 C34 C40 = Capacitor_ST: Capacitor 0402 / 0603 / 0805; Ordered by: Subcon
C10 C11 = Capacitor_ST: Capacitor 0402 / 0603 / 0805; Value: 100nF; Ordered by: Subcon
C26 = Cap_20pF_NPO_5%_0402: Capacitor,20pF,50V,NPO,5%,0402,YAGEO; Order: CC0402JRNPO9BN200; Fitted: NO; Ordered by: Subcon
C33 C38 = CAP SMD 0603  X5R 1µF 25V 10%: Capacitor; Value: 1µF; Rated voltage: 25V; Tolerance: 10%; Ordered by: Subcon
C39 = CAP SMD 0603  X7R 10000PF 50V 10%: 0603  X7R 10NF; Order code RS: 2040779; Rated voltage: 50V; Tolerance: 10%; Ordered by: Subcon
CN1 = USB-MINI-typeB connector: Manuf_Part_1: 5075BMR-05-SM; Manuf_Part_2: 218205M1110T; Manuf_2: lyconn; Description: USB,MINI-USB-5P/F, 5075BMR-05-M; Ordered by: Subcon; Silkscreen: USB ST-LINK
CN4 = Header 3X2: Header, 3-Pin, Dual row; Fitted: NO; Ordered by: Subcon
D1-D4 = BAT60JFILM: Provided: ST; ECCN_US/EU: EAR99/NEC; Ref St: 9151097
LD6 = HSMF-A201-A00J1: Ordered by: Subcon; ECCN_US/EU: EAR99/NEC; Silkscreen: COM
R8 = res1: Resistor; Value: 1K; Ordered by: Subcon
R9 R11 R16 R17 R21 R22 R25 R42 = Res1: Resistor; Value: 1K; Ordered by: Subcon
R12-R14 R20 = Resistor_ST: Resistor; Description: Resistor 0402 or 0603 or 0805; Value: 10K; Ordered by: Subcon
R15 R26 R27 R30 R32 R33 R35 R37 = Resistor_ST: Resistor 0402 / 0603 / 0805; Description: Resistor 0402 or 0603 or 0805; Value: 10K; Ordered by: Subcon
R28 R38 = Resistor_ST: Resistor; Description: Resistor 0402 or 0603 or 0805; Ordered by: Subcon
R29 R31 = Resistor_ST: Resistor 0402 / 0603 / 0805; Description: Resistor 0402 or 0603 or 0805; Value: 10K; Fitted: NO; Ordered by: Subcon
SB2 SB3 = Circuit Breaker: as SB1 on sheet Peripherals
SB4 SB16 = Circuit Breaker: Ordered by: Subcon; Comments: Solder bridge; Fitted: NO
T1 = NPN: NPN Bipolar Transistor; Manuf_Part_1: MMBT9013; Code - JEDEC: TO-226-AA; Ordered by: Subcon; ECCN_US/EU: EAR99/NEC
U3 = STM32F10x(48pin): Manuf_Part_1: STM32F103CBT6; Ordered by: ST; ECCN_US/EU: 3A991A2/NEC; Ref St: 9175111
U4 = ST890CDR: Ordered by: ST; Ref St: 9172002; ECCN_US/EU: EAR99/NEC
U9 = LD3985M33R: Ultra low drop-low noise BiCMOS voltage, regulators low ESR capacitors compatible; Manuf_1: ST; Ref St: 9176161; ECCN_US/EU: EAR99/NEC
X1 = XTAL_8M_NX3225GD: Crystal 8Mhz, 8pF, -+50PPM, SMD; Manuf_1: NDK; Manuf_Part_1: NX3225GD 8MHz EXS00A-CG04874; Manuf_Part_2: NX3225GD-8.000M-STD-CRA-3; ECCN_US/EU: EAR99/NEC; NDK Ref: X3127326; Ref St: 9157029; Provided: ST

## Sheet MCU.SchDoc: MCU
size A3; Date: 9/24/2014; Author: P.A.; CompanyName: STMicroelectronics; Organization: Microcontrollers Division; Address1: 12, Rue Jules HOROWITZ; Address2: 38019 Grenoble; Address3: FRANCE; DocumentNumber: MB1189; Revision: B-07; SheetNumber: 2; SheetTotal: 12; Project: STM32F469I-DISCO
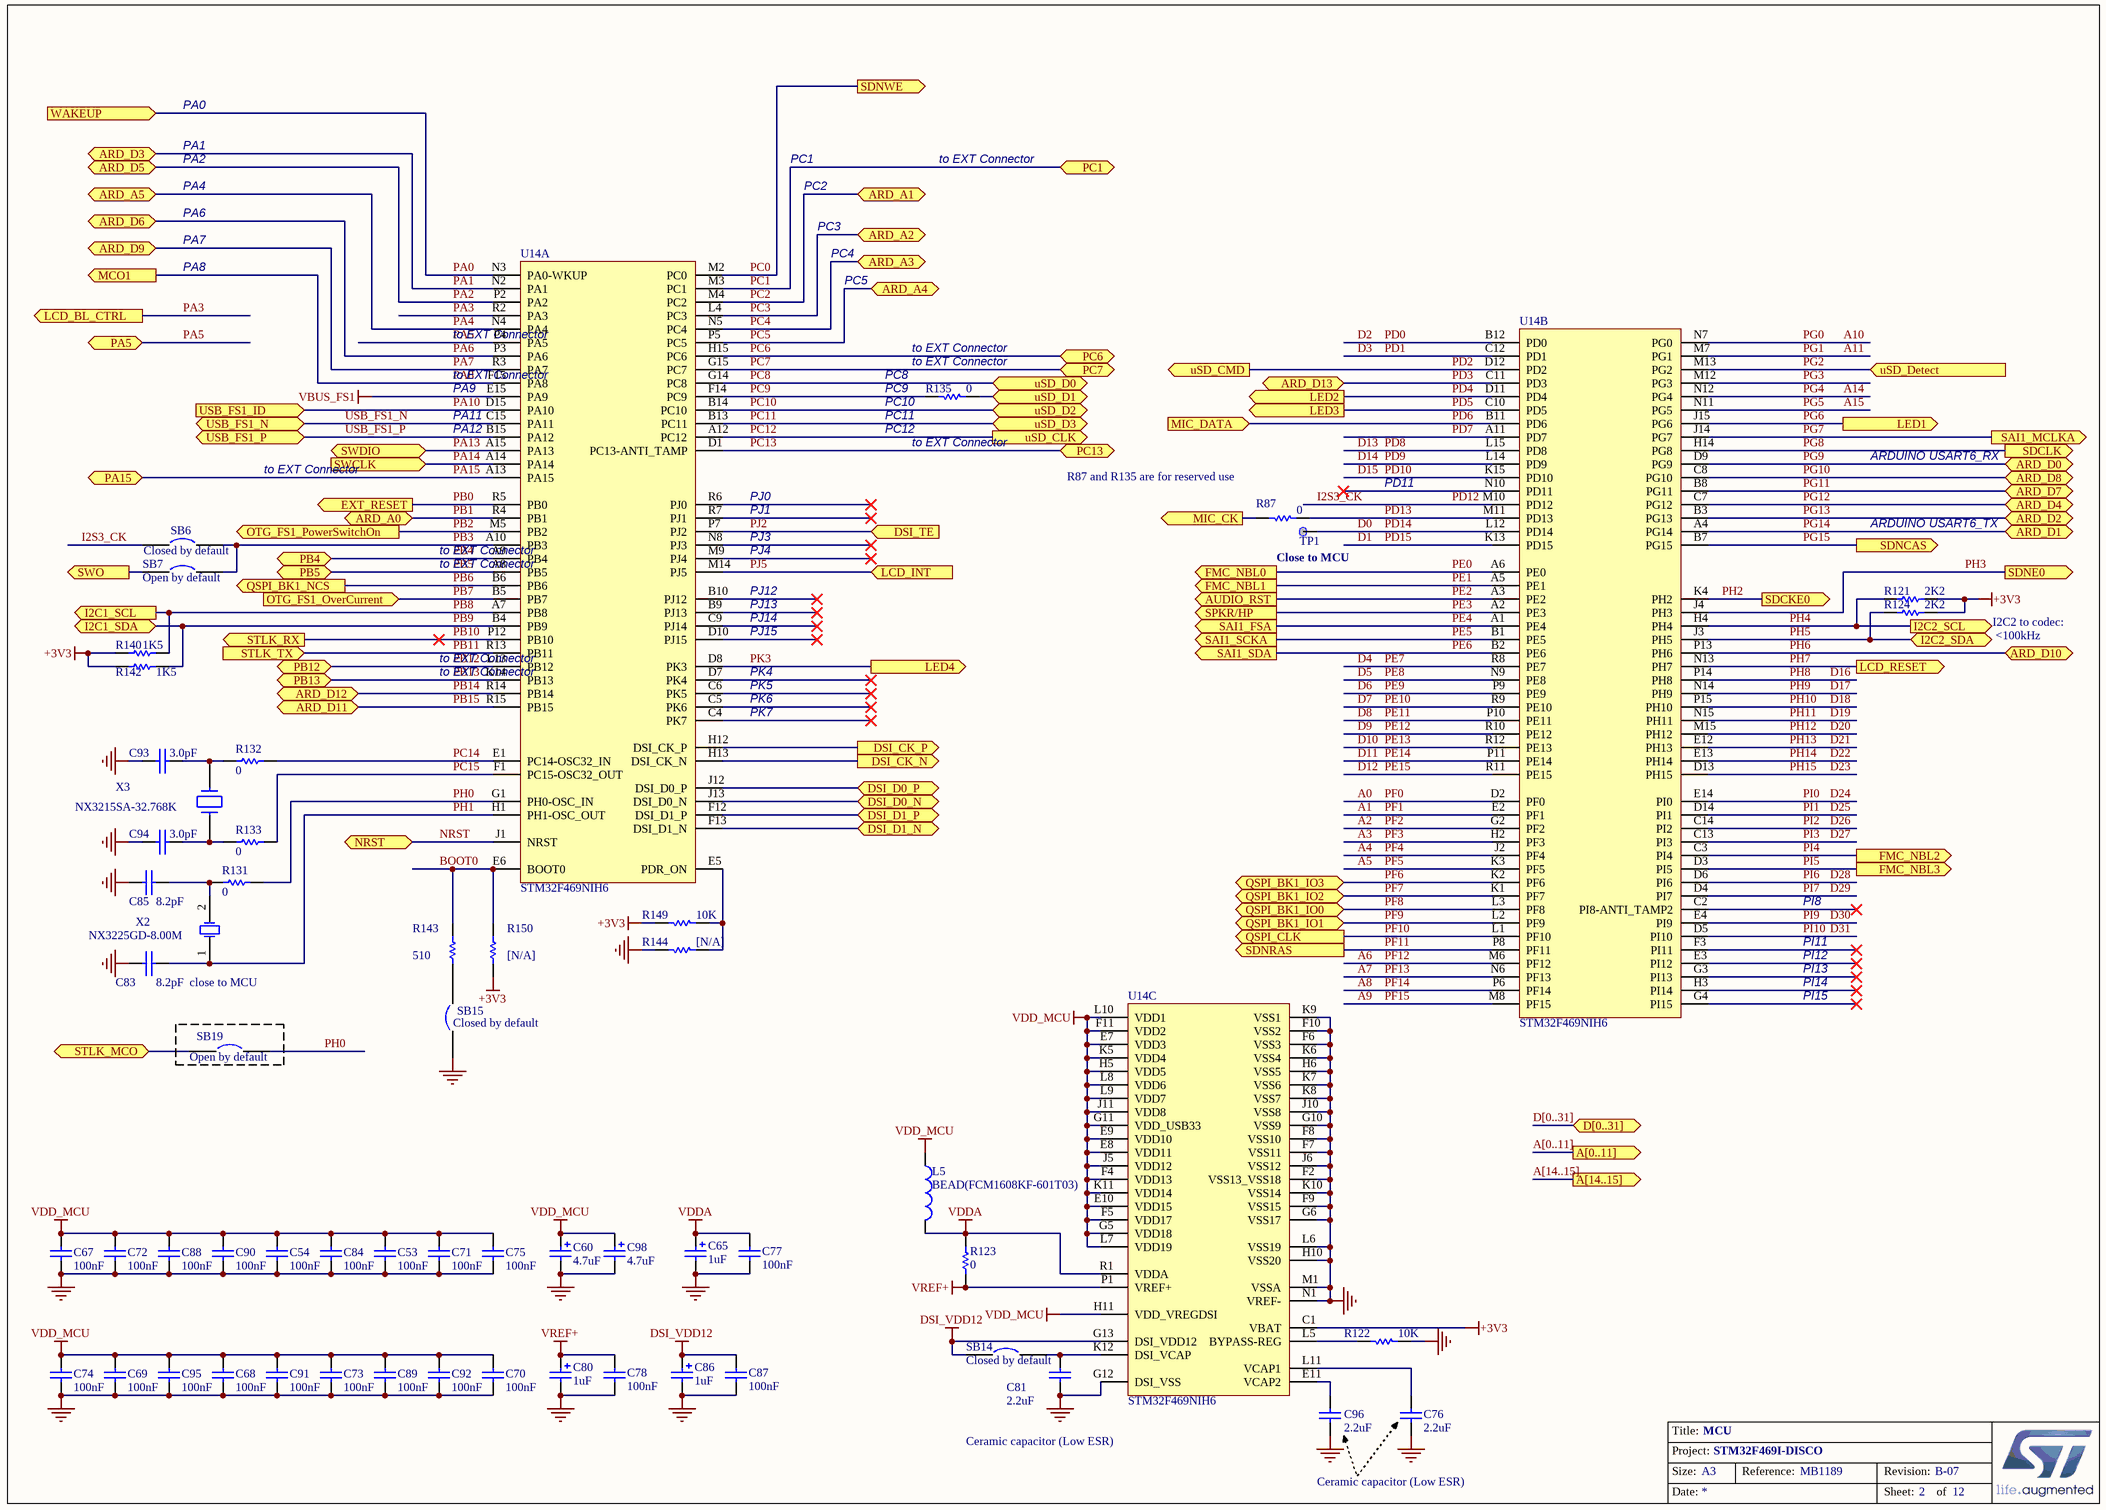
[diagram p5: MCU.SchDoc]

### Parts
C53  100nF  [0402C]
C54  100nF  [0402C]
C60  4.7uF  [TAN-A]
C65  1uF  [TAN-A]
C67  100nF  [0402C]
C68  100nF  [0402C]
C69  100nF  [0402C]
C70  100nF  [0402C]
C71  100nF  [0402C]
C72  100nF  [0402C]
C73  100nF  [0402C]
C74  100nF  [0402C]
C75  100nF  [0402C]
C76  2.2uF  [1206C]
C77  100nF  [0402C]
C78  100nF  [0402C]
C80  1uF  [TAN-A]
C81  2.2uF  [1206C]
C83  8.2pF  [0603C]
C84  100nF  [0402C]
C85  8.2pF  [0603C]
C86  1uF  [TAN-A]
C87  100nF  [0402C]
C88  100nF  [0402C]
C89  100nF  [0402C]
C90  100nF  [0402C]
C91  100nF  [0402C]
C92  100nF  [0402C]
C93  3.0pF  [0603C]
C94  3.0pF  [0603C]
C95  100nF  [0402C]
C96  2.2uF  [1206C]
C98  4.7uF  [TAN-A]
L5  BEAD(FCM1608KF-601T03)  [0603L]
R87  0  [0603R]
R121  2K2  [0603R]
R122  10K  [0402R]
R123  0  [0603R]
R124  2K2  [0603R]
R131  0  [0603R]
R132  0  [0603R]
R133  0  [0603R]
R135  0  [0603R]
R140  1K5  [0603R]
R142  1K5  [0603R]
R143  510  [0603R]
R144  [N/A]  [0603R]
R149  10K  [0402R]
R150  [N/A]  [0603R]
SB6  Closed by default  [SB_0603]
SB7  Open by default  [SB_0603]
SB14  Closed by default  [SB_0603]
SB15  Closed by default  [SB_0603]
SB19  Open by default  [SB_0603]
TP1  TP  [TP_C40]  (value not drawn)
U14  STM32F469NIH6  [BGA216_0R8_13X13]  (parts A,B,C of 3)
X2  NX3225GD-8.00M  [XTAL_2SM_3R2X2R5_H1]
X3  NX3215SA-32.768K  [XTAL_2SM_3R2X1R5]

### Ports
A[0..11] (out), A[14..15] (out), ARD_A0 (bidir), ARD_A1 (bidir), ARD_A2 (bidir), ARD_A3 (bidir), ARD_A4 (bidir), ARD_A5 (bidir), ARD_D0 (bidir), ARD_D1 (bidir), ARD_D2 (bidir), ARD_D3 (bidir), ARD_D4 (bidir), ARD_D5 (bidir), ARD_D6 (bidir), ARD_D7 (bidir), ARD_D8 (bidir), ARD_D9 (bidir), ARD_D10 (bidir), ARD_D11 (bidir), ARD_D12 (bidir), ARD_D13 (bidir), AUDIO_RST (out), D[0..31] (bidir), DSI_CK_N (out), DSI_CK_P (out), DSI_D0_N (bidir), DSI_D0_P (bidir), DSI_D1_N (bidir), DSI_D1_P (bidir), DSI_TE (in), EXT_RESET (out), FMC_NBL0 (out), FMC_NBL1 (out), FMC_NBL2 (out), FMC_NBL3 (out), I2C1_SCL (out), I2C1_SDA (bidir), I2C2_SCL (out), I2C2_SDA (bidir), LCD_BL_CTRL (out), LCD_INT (in), LCD_RESET (out), LED1 (out), LED2 (out), LED3 (out), LED4 (out), MCO1 (out), MIC_CK (out), MIC_DATA (in), NRST (bidir), OTG_FS1_OverCurrent (in), OTG_FS1_PowerSwitchOn (out), PA5 (bidir), PA15 (bidir), PB4 (bidir), PB5 (bidir), PB12 (bidir), PB13 (bidir), PC1 (bidir), PC6 (bidir), PC7 (bidir), PC13 (bidir), QSPI_BK1_IO0 (bidir), QSPI_BK1_IO1 (bidir), QSPI_BK1_IO2 (bidir), QSPI_BK1_IO3 (bidir), QSPI_BK1_NCS (out), QSPI_CLK (out), SAI1_FSA (out), SAI1_MCLKA (out), SAI1_SCKA (out), SAI1_SDA (out), SDCKE0 (out), SDCLK (out), SDNCAS (out), SDNE0 (out), SDNRAS (out), SDNWE (out), SPKR/HP (out), STLK_MCO, STLK_RX (out), STLK_TX (in), SWCLK (in), SWDIO, SWO (out), USB_FS1_ID (in), USB_FS1_N (bidir), USB_FS1_P (bidir), uSD_CLK (out), uSD_CMD (out), uSD_D0 (bidir), uSD_D1 (bidir), uSD_D2 (bidir), uSD_D3 (bidir), uSD_Detect (in), WAKEUP (in)

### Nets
+3V3: R121.1 R124.1 R140.1 R142.1 R149.2 R150.2 U14.C1(VBAT)
DSI_VDD12: C86.1 C87.2 SB14.1 U14.G13(DSI_VDD12)
GND: C53.2 C54.2 C60.2 C65.2 C67.2 C68.2 C69.2 C70.2 C71.2 C72.2 C73.2 C74.2 C75.2 C76.2 C77.1 C78.1 C80.2 C81.2 C83.2 C84.2 C85.2 C86.2 C87.1 C88.2 C89.2 C90.2 C91.2 C92.2 C93.2 C94.2 C95.2 C96.2 C98.2 R122.1 R144.2 SB15.1 U14.F2(VSS13_VSS18) U14.F6(VSS3) U14.F7(VSS11) U14.F8(VSS10) U14.F9(VSS15) U14.F10(VSS2) U14.G6(VSS17) U14.G10(VSS9) U14.G12(DSI_VSS) U14.H6(VSS5) U14.H10(VSS20) U14.J6(VSS12) U14.J10(VSS8) U14.K6(VSS4) U14.K7(VSS6) U14.K8(VSS7) U14.K9(VSS1) U14.K10(VSS14) U14.L6(VSS19) U14.M1(VSSA) U14.N1(VREF-)
VBUS_FS1: U14.E15(PA9)
VDD_MCU: C53.1 C54.1 C60.1 C67.1 C68.1 C69.1 C70.1 C71.1 C72.1 C73.1 C74.1 C75.1 C84.1 C88.1 C89.1 C90.1 C91.1 C92.1 C95.1 C98.1 L5.1 U14.E7(VDD3) U14.E8(VDD11) U14.E9(VDD10) U14.E10(VDD15) U14.F4(VDD13) U14.F5(VDD17) U14.F11(VDD2) U14.G5(VDD18) U14.G11(VDD_USB33) U14.H5(VDD5) U14.H11(VDD_VREGDSI) U14.J5(VDD12) U14.J11(VDD8) U14.K5(VDD4) U14.K11(VDD14) U14.L7(VDD19) U14.L8(VDD6) U14.L9(VDD7) U14.L10(VDD1)
VDDA: C65.1 C77.2 L5.2 R123.1 U14.R1(VDDA)
VREF+: C78.2 C80.1 R123.2 U14.P1(VREF+)
A0: U14.D2(PF0)  [also labelled PF0]
A1: U14.E2(PF1)  [also labelled PF1]
A2: U14.G2(PF2)  [also labelled PF2]
A3: U14.H2(PF3)  [also labelled PF3]
A4: U14.J2(PF4)  [also labelled PF4]
A5: U14.K3(PF5)  [also labelled PF5]
A6: U14.M6(PF12)  [also labelled PF12]
A7: U14.N6(PF13)  [also labelled PF13]
A8: U14.P6(PF14)  [also labelled PF14]
A9: U14.M8(PF15)  [also labelled PF15]
A10: U14.N7(PG0)  [also labelled PG0]
A11: U14.M7(PG1)  [also labelled PG1]
A14: U14.N12(PG4)  [also labelled PG4]
A15: U14.N11(PG5)  [also labelled PG5]
BOOT0: R143.1 R150.1 U14.E6(BOOT0)
D0: TP1.1 U14.L12(PD14)  [also labelled PD14]
D1: U14.K13(PD15)  [also labelled PD15]
D2: U14.B12(PD0)  [also labelled PD0]
D3: U14.C12(PD1)  [also labelled PD1]
D4: U14.R8(PE7)  [also labelled PE7]
D5: U14.N9(PE8)  [also labelled PE8]
D6: U14.P9(PE9)  [also labelled PE9]
D7: U14.R9(PE10)  [also labelled PE10]
D8: U14.P10(PE11)  [also labelled PE11]
D9: U14.R10(PE12)  [also labelled PE12]
D10: U14.R12(PE13)  [also labelled PE13]
D11: U14.P11(PE14)  [also labelled PE14]
D12: U14.R11(PE15)  [also labelled PE15]
D13: U14.L15(PD8)  [also labelled PD8]
D14: U14.L14(PD9)  [also labelled PD9]
D15: U14.K15(PD10)  [also labelled PD10]
D16: U14.P14(PH8)  [also labelled PH8]
D17: U14.N14(PH9)  [also labelled PH9]
D18: U14.P15(PH10)  [also labelled PH10]
D19: U14.N15(PH11)  [also labelled PH11]
D20: U14.M15(PH12)  [also labelled PH12]
D21: U14.E12(PH13)  [also labelled PH13]
D22: U14.E13(PH14)  [also labelled PH14]
D23: U14.D13(PH15)  [also labelled PH15]
D24: U14.E14(PI0)  [also labelled PI0]
D25: U14.D14(PI1)  [also labelled PI1]
D26: U14.C14(PI2)  [also labelled PI2]
D27: U14.C13(PI3)  [also labelled PI3]
D28: U14.D6(PI6)  [also labelled PI6]
D29: U14.D4(PI7)  [also labelled PI7]
D30: U14.E4(PI9)  [also labelled PI9]
D31: U14.D5(PI10)  [also labelled PI10]
HSSI_CLK_N: U14.H13(DSI_CK_N) ; port DSI_CK_N
HSSI_CLK_P: U14.H12(DSI_CK_P) ; port DSI_CK_P
HSSI_D0_N: U14.J13(DSI_D0_N) ; port DSI_D0_N
HSSI_D0_P: U14.J12(DSI_D0_P) ; port DSI_D0_P
HSSI_D1_N: U14.F13(DSI_D1_N) ; port DSI_D1_N
HSSI_D1_P: U14.F12(DSI_D1_P) ; port DSI_D1_P
I2S3_CK: SB6.1 U14.M10(PD12)  [also labelled PD12]
NRST: U14.J1(NRST) ; port NRST
PA0: U14.N3(PA0-WKUP) ; port WAKEUP
PA1: U14.N2(PA1) ; port ARD_D3
PA2: U14.P2(PA2) ; port ARD_D5
PA3: U14.R2(PA3) ; port LCD_BL_CTRL  [project net LCD_BL_CTRL]
PA4: U14.N4(PA4) ; port ARD_A5
PA5: U14.P4(PA5) ; port PA5
PA6: U14.P3(PA6) ; port ARD_D6
PA7: U14.R3(PA7) ; port ARD_D9
PA8: U14.F15(PA8) ; port MCO1
PA10: U14.D15(PA10) ; port USB_FS1_ID
PA13: U14.A15(PA13) ; port SWDIO
PA14: U14.A14(PA14) ; port SWCLK
PA15: U14.A13(PA15) ; port PA15
PB0: U14.R5(PB0) ; port EXT_RESET
PB1: U14.R4(PB1) ; port ARD_A0
PB2: U14.M5(PB2) ; port OTG_FS1_PowerSwitchOn
PB3: SB6.2 SB7.2 U14.A10(PB3)
PB4: U14.A9(PB4) ; port PB4
PB5: U14.A8(PB5) ; port PB5
PB6: U14.B6(PB6) ; port QSPI_BK1_NCS
PB7: U14.B5(PB7) ; port OTG_FS1_OverCurrent
PB8: R140.2 U14.A7(PB8) ; port I2C1_SCL  [project net I2C1_SCL]
PB9: R142.2 U14.B4(PB9) ; port I2C1_SDA  [project net I2C1_SDA]
PB10: U14.P12(PB10) ; port STLK_RX
PB11: U14.R13(PB11) ; port STLK_TX
PB12: U14.L13(PB12) ; port PB12
PB13: U14.K14(PB13) ; port PB13
PB14: U14.R14(PB14) ; port ARD_D12
PB15: U14.R15(PB15) ; port ARD_D11
PC0: U14.M2(PC0) ; port SDNWE
PC1: U14.M3(PC1) ; port PC1
PC2: U14.M4(PC2) ; port ARD_A1
PC3: U14.L4(PC3) ; port ARD_A2
PC4: U14.N5(PC4) ; port ARD_A3
PC5: U14.P5(PC5) ; port ARD_A4
PC6: U14.H15(PC6) ; port PC6
PC7: U14.G15(PC7) ; port PC7
PC8: U14.G14(PC8) ; port uSD_D0
PC9: R135.1 U14.F14(PC9)
PC10: U14.B14(PC10) ; port uSD_D2
PC11: U14.B13(PC11) ; port uSD_D3
PC12: U14.A12(PC12) ; port uSD_CLK
PC13: U14.D1(PC13-ANTI_TAMP) ; port PC13
PC14: R132.2 U14.E1(PC14-OSC32_IN)
PC15: R133.2 U14.F1(PC15-OSC32_OUT)
PD2: U14.D12(PD2) ; port uSD_CMD
PD3: U14.C11(PD3) ; port ARD_D13
PD4: U14.D11(PD4) ; port LED2
PD5: U14.C10(PD5) ; port LED3
PD6: U14.B11(PD6) ; port MIC_DATA
PD7: U14.A11(PD7)
PD13: R87.2 U14.M11(PD13)
PE0: U14.A6(PE0) ; port FMC_NBL0
PE1: U14.A5(PE1) ; port FMC_NBL1
PE2: U14.A3(PE2) ; port AUDIO_RST  [project net AUDIO_RST]
PE3: U14.A2(PE3) ; port SPKR/HP
PE4: U14.A1(PE4) ; port SAI1_FSA
PE5: U14.B1(PE5) ; port SAI1_SCKA
PE6: U14.B2(PE6) ; port SAI1_SDA
PF6: U14.K2(PF6) ; port QSPI_BK1_IO3
PF7: U14.K1(PF7) ; port QSPI_BK1_IO2
PF8: U14.L3(PF8) ; port QSPI_BK1_IO0
PF9: U14.L2(PF9) ; port QSPI_BK1_IO1
PF10: U14.L1(PF10) ; port QSPI_CLK
PF11: U14.P8(PF11) ; port SDNRAS
PG2: U14.M13(PG2) ; port uSD_Detect
PG3: U14.M12(PG3)
PG6: U14.J15(PG6) ; port LED1
PG7: U14.J14(PG7) ; port SAI1_MCLKA
PG8: U14.H14(PG8) ; port SDCLK
PG9: U14.D9(PG9) ; port ARD_D0
PG10: U14.C8(PG10) ; port ARD_D8
PG11: U14.B8(PG11) ; port ARD_D7
PG12: U14.C7(PG12) ; port ARD_D4
PG13: U14.B3(PG13) ; port ARD_D2
PG14: U14.A4(PG14) ; port ARD_D1
PG15: U14.B7(PG15) ; port SDNCAS
PH0: R131.1 SB19.2 U14.G1(PH0-OSC_IN)
PH1: C83.1 U14.H1(PH1-OSC_OUT) X2.1(OSC1)
PH2: U14.K4(PH2) ; port SDCKE0
PH3: U14.J4(PH3) ; port SDNE0
PH4: R121.2 U14.H4(PH4) ; port I2C2_SCL  [project net I2C2_SCL]
PH5: R124.2 U14.J3(PH5) ; port I2C2_SDA  [project net I2C2_SDA]
PH6: U14.P13(PH6) ; port ARD_D10
PH7: U14.N13(PH7) ; port LCD_RESET  [project net LCD_RST]
PI4: U14.C3(PI4) ; port FMC_NBL2
PI5: U14.D3(PI5) ; port FMC_NBL3
PJ2: U14.P7(PJ2) ; port DSI_TE
PJ5: U14.M14(PJ5) ; port LCD_INT  [project net LCD_INT]
PK3: U14.D8(PK3) ; port LED4
USB_FS1_N: U14.C15(PA11) ; port USB_FS1_N
USB_FS1_P: U14.B15(PA12) ; port USB_FS1_P
NetC26_1: SB19.1 ; port STLK_MCO
NetC76_1: C76.1 U14.L11(VCAP1)
NetC81_1: C81.1 SB14.2 U14.K12(DSI_VCAP)
NetC85_1: C85.1 R131.2 X2.2(OSC2)
NetC93_1: C93.1 R132.1 X3.1
NetC94_1: C94.1 R133.1 X3.2
NetC96_1: C96.1 U14.E11(VCAP2)
NetCN9_8: R135.2 ; port uSD_D1
NetR87_1: R87.1 ; port MIC_CK
NetR122_2: R122.2 U14.L5(BYPASS-REG)
NetR143_2: R143.2 SB15.2
NetR144_1: R144.1 R149.1 U14.E5(PDR_ON)
NetSB3_2: SB7.1 ; port SWO

Not connected (* = marked no-connect by the designer): U14 B9(PJ13)* B10(PJ12)* C2(PI8-ANTI_TAMP2)* C4(PK7)* C5(PK6)* C6(PK5)* C9(PJ14)* D7(PK4)* D10(PJ15)* E3(PI12)* F3(PI11)* G3(PI13)* G4(PI15)* H3(PI14)* M9(PJ4)* N8(PJ3)* N10(PD11)* R6(PJ0)* R7(PJ1)*

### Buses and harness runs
bus A[0..11] = port A[0..11]
bus A[14..15] = port A[14..15]
bus D[0..31] = port D[0..31]

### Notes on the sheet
- PA0
- PA1
- PA2
- PC1
- to EXT Connector
- PA6
- PA7
- PA4
- PC2
- PC3
- PA8
- PC4
- PC5
- (near R135) PC8
- (near R135) to EXT Connector
- (near U14) PA11
- (near U14) PA12
- (near U14) PA9
- (near R135) PC9
- (near R135) PC10
- (near R135) PC11
- (near R135) PC12
- PJ1
- PJ0
- (near R87) R87 and R135 are for reserved use
- PD11
- ARDUINO USART6_RX
- PJ4
- PJ3
- Close to MCU
- ARDUINO USART6_TX
- PJ15
- PJ13
- PJ12
- PJ14
- I2C2 to codec:
  <100kHz
- PK7
- PK6
- PK5
- PK4
- PI8
- close to MCU
- PI14
- PI13
- PI12
- PI11
- PI15
- Ceramic capacitor (Low ESR)

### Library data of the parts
C53 C54 C67-C75 C83-C85 C88-C95 = CAP: Capacitor; Ordered by: Subcon
C60 C98 = Cap Pol1: Polarized Capacitor (Radial); Value: 47uF; Ordered by: Subcon
C65 C80 C86 = Cap Pol1: Polarized Capacitor (Radial); Value: 10uF; Ordered by: Subcon
C76-C78 C81 C87 C96 = Cap: as C42 on sheet Memory
L5 = Inductor: Value: 100uH; Ordered by: Subcon
R87 R121-R124 R131-R133 R135 R140 R142 R149 = Res1: Resistor; Value: 1K; Ordered by: Subcon
R143 = res1: Resistor; Value: 1K; Ordered by: Subcon
R144 = Res1: Resistor; Value: 1K; Ordered by: Subcon; Fitted: NO
R150 = res1: Resistor; Value: 1K; Ordered by: Subcon; Fitted: NO
SB6 SB14 SB15 = Circuit Breaker: as SB1 on sheet Peripherals
SB7 SB19 = Circuit Breaker: as SB4 on sheet ST_LINK_V2-1
TP1 = TP: Ordered by: Subcon
U14 = Manta_Dragon_TFBGA216: Manuf_Part_1: STM32F469NIH6U cut 1.0; Ordered by: ST; Ref St: 9175177; ECCN_US/EU: 3A991A2/NEC
X2 = XTAL_8M_NX3225GD: as X1 on sheet ST_LINK_V2-1
X3 = XTAL_32K_NX3215SA: Crystal 32.768kHz, 6pF, -+20PPM, R=50K, SMD; Manuf_1: NDK; Manuf_Part_1: NX3215SA 32.768KHz EXS00A-MU00525; Description: Crystal 32.768kHz, 6pF, -+20PPM, NDK only for ST, Type NX3215SA,  NDK Spec EXS00A-MU00525; ECCN_US/EU: EAR99/NEC; Ref St: 9157034; NDK Ref: X3101802; Provided: ST

## Sheet Arduino_ Connectors.SchDoc: Arduino Uno connector
size A4; Date: 9/24/2014; Author: P.A.; CompanyName: STMicroelectronics; Organization: Microcontrollers Division; Address1: 12, Rue Jules HOROWITZ; Address2: 38019 Grenoble; Address3: FRANCE; DocumentNumber: MB1189; Revision: B-07; SheetNumber: 11; SheetTotal: 12; Project: STM32F469I-DISCO
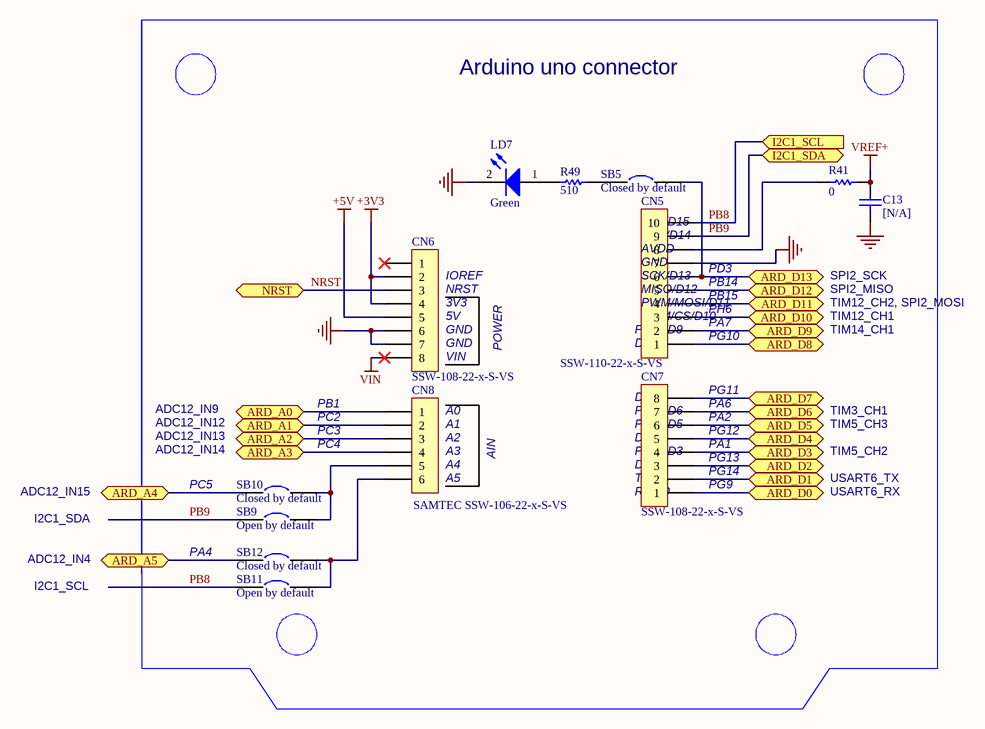
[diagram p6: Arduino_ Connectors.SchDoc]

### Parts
C13  [N/A]  [0603C]
CN5  SSW-110-22-x-S-VS  [SSW-110-22-X-S-VS]
CN6  SSW-108-22-x-S-VS  [SSW-108-22-X-S-VS]
CN7  SSW-108-22-x-S-VS  [SSW-108-22-X-S-VS]
CN8  SAMTEC SSW-106-22-x-S-VS  [SSW-106-22-X-S-VS]
LD7  Green  [0603D]
R41  0  [0603R]
R49  510  [0603R]
SB5  Closed by default  [SB_0603]
SB9  Open by default  [SB_0603]
SB10  Closed by default  [SB_0603]
SB11  Open by default  [SB_0603]
SB12  Closed by default  [SB_0603]

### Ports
ARD_A0 (bidir), ARD_A1 (bidir), ARD_A2 (bidir), ARD_A3 (bidir), ARD_A4 (bidir), ARD_A5 (bidir), ARD_D0 (bidir), ARD_D1 (bidir), ARD_D2 (bidir), ARD_D3 (bidir), ARD_D4 (bidir), ARD_D5 (bidir), ARD_D6 (bidir), ARD_D7 (bidir), ARD_D8 (bidir), ARD_D9 (bidir), ARD_D10 (bidir), ARD_D11 (bidir), ARD_D12 (bidir), ARD_D13 (bidir), I2C1_SCL (in), I2C1_SDA (bidir), NRST (bidir)

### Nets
+3V3: CN6.2 CN6.4
+5V: CN6.5
GND: C13.1 CN5.7 CN6.6 CN6.7 LD7.2(K)
VIN: CN6.8
VREF+: C13.2 R41.1
NRST: CN6.3 ; port NRST
PA1: CN7.4 ; port ARD_D3
PA2: CN7.6 ; port ARD_D5
PA4: SB12.1 ; port ARD_A5
PA6: CN7.7 ; port ARD_D6
PA7: CN5.2 ; port ARD_D9
PB1: CN8.1 ; port ARD_A0
PB8: CN5.10 SB11.1 ; port I2C1_SCL  [project net I2C1_SCL]
PB9: CN5.9 SB9.1 ; port I2C1_SDA  [project net I2C1_SDA]
PB14: CN5.5 ; port ARD_D12
PB15: CN5.4 ; port ARD_D11
PC2: CN8.2 ; port ARD_A1
PC3: CN8.3 ; port ARD_A2
PC4: CN8.4 ; port ARD_A3
PC5: SB10.1 ; port ARD_A4
PD3: CN5.6 SB5.2 ; port ARD_D13
PG9: CN7.1 ; port ARD_D0
PG10: CN5.1 ; port ARD_D8
PG11: CN7.8 ; port ARD_D7
PG12: CN7.5 ; port ARD_D4
PG13: CN7.3 ; port ARD_D2
PG14: CN7.2 ; port ARD_D1
PH6: CN5.3 ; port ARD_D10
NetCN5_8: CN5.8 R41.2
NetCN8_5: CN8.5 SB9.2 SB10.2
NetCN8_6: CN8.6 SB11.2 SB12.2
NetLD7_1: LD7.1(A) R49.2
NetR49_1: R49.1 SB5.1

Not connected (* = marked no-connect by the designer): CN6 1*

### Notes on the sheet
- Arduino uno connector
- (near CN5) SDA/D14
- SCL/D15
- (near CN5) AVDD
- (near CN6) IOREF
- (near CN6) NRST
- (near CN6) 3V3
- (near CN5) SCK/D13
- (near CN5) MISO/D12
- (near CN5) PWM/MOSI/D11
- (near CN5) GND
- (near CN5) PH6
- (near CN5) PB15
- (near CN5) PB14
- (near CN5) PD3
- TIM12_CH2, SPI2_MOSI
- SPI2_MISO
- SPI2_SCK
- (near CN6) 5V
- (near CN6) GND
- (near CN6) VIN
- POWER
- (near CN5) D8
- (near CN5) PWM/D9
- (near CN5) PWM/CS/D10
- (near CN5) PG10
- (near CN5) PA7
- TIM14_CH1
- TIM12_CH1
- ADC12_IN14
- ADC12_IN13
- ADC12_IN12
- ADC12_IN9
- PB1
- PC2
- PC3
- PC4
- (near CN8) A0
- (near CN8) A1
- (near CN8) A2
- (near CN7) D4
- (near CN7) PWM/D5
- (near CN7) PWM/D6
- (near CN7) D7
- (near CN7) PA1
- (near CN7) PG12
- (near CN7) PA2
- (near CN7) PA6
- PG11
- TIM5_CH3
- TIM3_CH1
- ADC12_IN15
- I2C1_SDA
- PC5
- (near CN8) A3
- (near CN8) A4
- (near CN8) A5
- AIN
- (near CN7) RX/D0
- (near CN7) TX/D1
- (near CN7) D2
- (near CN7) PWM/D3
- (near CN7) PG9
- (near CN7) PG14
- (near CN7) PG13
- USART6_RX
- USART6_TX
- TIM5_CH2
- ADC12_IN4
- PA4
- I2C1_SCL

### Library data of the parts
C13 = Cap: Capacitor; Value: 10nF; Ordered by: Subcon; Fitted: NO
CN5 = Header 10X1_Female: Header, 10-Pin, Single row,female; Manuf_1: SAMTEC; Ordered by: Subcon; Silkscreen: pin names as in schematic
CN6 CN7 = Header 8X1_Female: Header, 8-Pin, Single row,female; Manuf_1: SAMTEC; Ordered by: Subcon; Silkscreen: pin names as in schematic
CN8 = Header 6X1_Female: Header, 6-Pin, Single row,female SMD; Ordered by: Subcon; Silkscreen: pin names as in schematic
LD7 = LED2: as LD1 on sheet Peripherals
R41 R49 = Res1: Resistor; Value: 1K; Ordered by: Subcon
SB5 SB10 SB12 = Circuit Breaker: as SB1 on sheet Peripherals
SB9 SB11 = Circuit Breaker: as SB4 on sheet ST_LINK_V2-1

## Sheet DSI_LCD.SchDoc: 4 inch DSI LCD board
size A4; Date: 9/24/2014; Author: P.A.; CompanyName: STMicroelectronics; Organization: Microcontrollers Division; Address1: 12, Rue Jules HOROWITZ; Address2: 38019 Grenoble; Address3: FRANCE; DocumentNumber: MB1189; Revision: B-07; SheetNumber: 7; SheetTotal: 12; Project: STM32F469I-DISCO
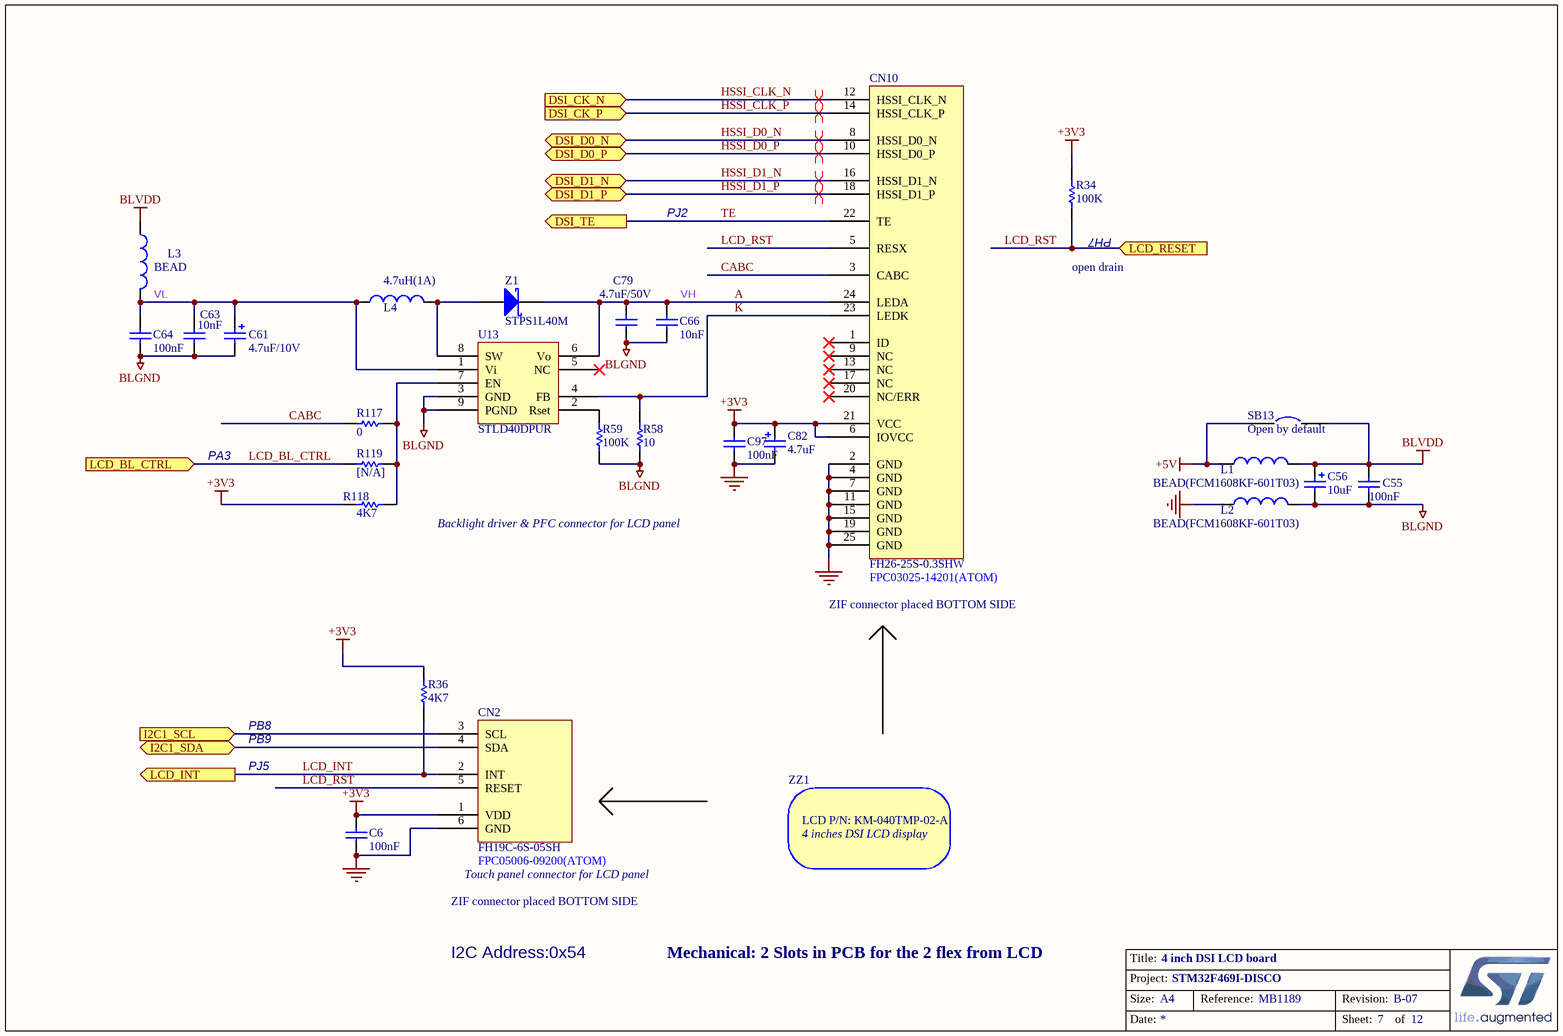
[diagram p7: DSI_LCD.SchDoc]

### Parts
C6  100nF  [0402C]
C55  100nF  [0402C]
C56  10uF  [TAN-A]
C61  4.7uF/10V  [1206C]
C63  10nF  [0603C]
C64  100nF  [0402C]
C66  10nF  [0603C]
C79  4.7uF/50V  [1206C]
C82  4.7uF  [TAN-A]
C97  100nF  [0402C]
CN2  FH19C-6S-05SH  [FH19C-6S-0R5SH_FPC_CPT]
CN10  FH26-25S-0.3SHW  [FPC25_FPC03025-1420]
L1  BEAD(FCM1608KF-601T03)  [0603L]
L2  BEAD(FCM1608KF-601T03)  [0603L]
L3  BEAD  [0603L]
L4  4.7uH(1A)  [1210L]
R34  100K  [0402R]
R36  4K7  [0603R]
R58  10  [0603R]
R59  100K  [0603R]
R117  0  [0603R]
R118  4K7  [0603R]
R119  [N/A]  [0603R]
SB13  Open by default  [SB_0603]
U13  STLD40DPUR  [SON8_0R65_3X3]
Z1  STPS1L40M  [DO-216AA]
ZZ1  LCD P/N: KM-040TMP-02-A

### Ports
DSI_CK_N (in), DSI_CK_P (in), DSI_D0_N (bidir), DSI_D0_P (bidir), DSI_D1_N (bidir), DSI_D1_P (bidir), DSI_TE (out), I2C1_SCL (in), I2C1_SDA (bidir), LCD_BL_CTRL (in), LCD_INT (out), LCD_RESET (in)

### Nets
+3V3: C6.2 C82.1 C97.2 CN2.1(VDD) CN10.6(IOVCC) CN10.21(VCC) R34.1 R36.1 R118.2
+5V: L1.1 SB13.1
BLGND: C55.2 C56.2 C61.2 C63.1 C64.1 C66.1 C79.2 L2.2 R58.1 R59.2 U13.3(GND) U13.9(PGND)
BLVDD: C55.1 C56.1 L1.2 L3.1 SB13.2
GND: C6.1 C82.2 C97.1 CN2.6(GND) CN10.2(GND) CN10.4(GND) CN10.7(GND) CN10.11(GND) CN10.15(GND) CN10.19(GND) CN10.25(GND) L2.1
A: C66.2 C79.1 CN10.24(LEDA) U13.6(Vo) Z1.2(K)  [also labelled VH]
CABC: CN10.3(CABC) R117.2
HSSI_CLK_N: CN10.12(HSSI_CLK_N) ; port DSI_CK_N
HSSI_CLK_P: CN10.14(HSSI_CLK_P) ; port DSI_CK_P
HSSI_D0_N: CN10.8(HSSI_D0_N) ; port DSI_D0_N
HSSI_D0_P: CN10.10(HSSI_D0_P) ; port DSI_D0_P
HSSI_D1_N: CN10.16(HSSI_D1_N) ; port DSI_D1_N
HSSI_D1_P: CN10.18(HSSI_D1_P) ; port DSI_D1_P
I2C1_SCL: CN2.3(SCL) ; port I2C1_SCL
I2C1_SDA: CN2.4(SDA) ; port I2C1_SDA
K: CN10.23(LEDK) R58.2 U13.4(FB)
LCD_BL_CTRL: R119.2 ; port LCD_BL_CTRL
LCD_INT: CN2.2(INT) R36.2 ; port LCD_INT
LCD_RST: CN2.5(RESET) CN10.5(RESX) R34.2 ; port LCD_RESET
TE: CN10.22(TE) ; port DSI_TE  [project net PJ2]
VL: C61.1 C63.2 C64.2 L3.2 L4.1 U13.1(Vi)
NetL4_2: L4.2 U13.8(SW) Z1.1(A)
NetR59_1: R59.1 U13.2(Rset)
NetR117_1: R117.1 R118.1 R119.1 U13.7(EN)

Not connected (* = marked no-connect by the designer): CN10 1(ID)* 9(NC)* 13(NC)* 17(NC)* 20(NC/ERR)*; U13 5(NC)*

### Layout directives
differential pair: HSSI_CLK_N, HSSI_CLK_P, HSSI_D0_N, HSSI_D0_P, HSSI_D1_N, HSSI_D1_P

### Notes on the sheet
- PJ2
- (near R34) PH7
- open drain
- PA3
- Backlight driver & PFC connector for LCD panel
- (near CN10) FPC03025-14201(ATOM)
- ZIF connector placed BOTTOM SIDE
- PB9
- PB8
- PJ5
- (near ZZ1) 4 inches DSI LCD display
- (near CN2) Touch panel connector for LCD panel
- (near CN2) FPC05006-09200(ATOM)
- I2C Address:0x54
- Mechanical: 2 Slots in PCB for the 2 flex from LCD

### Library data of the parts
C6 C63 C64 C66 C79 C97 = CAP: as C3 on sheet Peripherals
C55 = Cap: as C42 on sheet Memory
C56 = Cap Pol1: as C29 on sheet Power
C61 C82 = Cap Pol1: Polarized Capacitor (Radial); Value: 100pF; Ordered by: Subcon
CN2 = FH19C-6S-05SH: ZIF connector placed bottom side; Manuf_1: ATOM; Manuf_2: Hirose; Manuf_Part_1: FPC05006-09200; Ordered by: Subcon; Silkscreen: TS
CN10 = FH26-25S-0.3SHW: ZIF connector placed bottom side; Manuf_1: ATOM; Manuf_Part_1: FPC03025-14201; Manuf_2: Hirose; Ordered by: Subcon; Comments: Hirose FH26-25S-0.3SHW; Silkscreen: DSI LCD
L1-L4 = Inductor: Value: 100uH; Ordered by: Subcon
R34 R36 R58 R59 R117 R118 = Res1: Resistor; Value: 1K; Ordered by: Subcon
R119 = Res1: as R144 on sheet MCU
SB13 = Circuit Breaker: as SB4 on sheet ST_LINK_V2-1
U13 = STLD40DPMR: Ordered by: ST; Ref St: 9176009; ECCN_US/EU: EAR99/NEC
Z1 = D Schottky: Schottky Diode; Code - JEDEC: DO-214-AA; Ordered by: ST; Ref St: 9151085; ECCN_US/EU: EAR99/NEC
ZZ1 = BoM_Item: 4 inches DSI LCD with touch screen; Manuf_1: KOD; Ordered by: Subcon; Comments: 4 inches DSI LCD display; ECCN_US/EU: EAR99/NEC

## Sheet QSPI.SchDoc: QSPI
size A4; Date: 9/24/2014; Author: P.A.; CompanyName: STMicroelectronics; Organization: Microcontrollers Division; Address1: 12, Rue Jules HOROWITZ; Address2: 38019 Grenoble; Address3: FRANCE; DocumentNumber: MB1189; Revision: B-07; SheetNumber: 9; SheetTotal: 12; Project: STM32F469I-DISCO
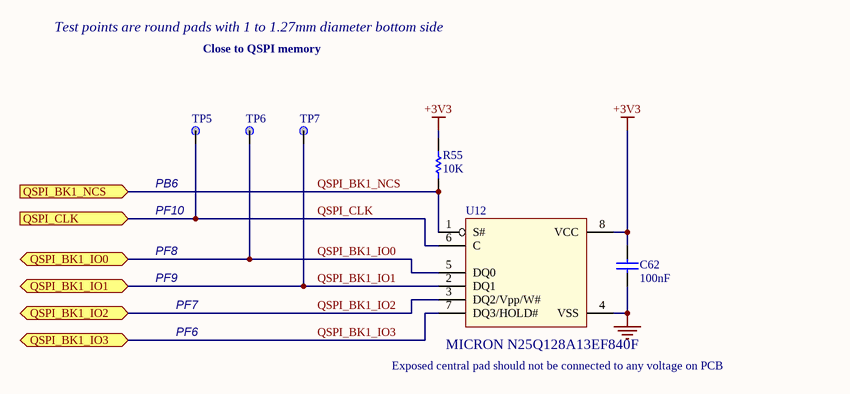
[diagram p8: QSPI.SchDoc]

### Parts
C62  100nF  [0402C]
R55  10K  [0402R]
TP5  TP  [TP_C40]  (value not drawn)
TP6  TP  [TP_C40]  (value not drawn)
TP7  TP  [TP_C40]  (value not drawn)
U12  MICRON N25Q128A13EF840F  [DFN8_1R27_6X8_TP4R8X5R8]

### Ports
QSPI_BK1_IO0 (bidir), QSPI_BK1_IO1 (bidir), QSPI_BK1_IO2 (bidir), QSPI_BK1_IO3 (bidir), QSPI_BK1_NCS (in), QSPI_CLK (in)

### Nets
+3V3: C62.1 R55.2 U12.8(VCC)
GND: C62.2 U12.4(VSS)
QSPI_BK1_IO0: TP6.1 U12.5(DQ0) ; port QSPI_BK1_IO0  [project net PF8]
QSPI_BK1_IO1: TP7.1 U12.2(DQ1) ; port QSPI_BK1_IO1  [project net PF9]
QSPI_BK1_IO2: U12.3(DQ2/Vpp/W#) ; port QSPI_BK1_IO2  [project net PF7]
QSPI_BK1_IO3: U12.7(DQ3/HOLD#) ; port QSPI_BK1_IO3  [project net PF6]
QSPI_BK1_NCS: R55.1 U12.1(S#) ; port QSPI_BK1_NCS  [project net PB6]
QSPI_CLK: TP5.1 U12.6(C) ; port QSPI_CLK  [project net PF10]

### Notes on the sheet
- Test points are round pads with 1 to 1.27mm diameter bottom side
- Close to QSPI memory
- (near TP5) PB6
- PF10
- PF8
- PF9
- PF7
- PF6
- (near U12) Exposed central pad should not be connected to any voltage on PCB

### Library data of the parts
C62 = Cap: as C42 on sheet Memory
R55 = Res_10K_1%_0402: Resistor; Manuf_Part_1: RC0402FR-0710KL; Manuf_1: YAGEO; Description: Resistor,10K,0402,1%,YAGEO; Ordered by: Subcon
TP5-TP7 = TP: Ordered by: Subcon
U12 = N25Q128A13EF840E: 128Mb, 3V, Multiple I/O Serial Flash Memory, Quad/Dual; Manuf_Part_2: N25Q256A13EF840E; Manuf_Part_3: N25Q512A13EF840E; ECCN_US/EU: 3A991/NEC; Order: N25Q128A13EF840F-ND; Ordered by: Subcon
